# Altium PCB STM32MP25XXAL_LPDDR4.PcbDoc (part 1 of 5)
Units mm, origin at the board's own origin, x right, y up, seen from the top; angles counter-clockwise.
Board outline 125 x 95 mm, 6 copper layers (Top Layer, Signal Layer 1, Signal Layer 2, Signal Layer 3, Signal Layer 4, Bottom Layer), stack 1.403 mm thick; 182 components, 297 nets, 1131 pads, 958 vias.
Unrouted connection lines stored in the file: 5.
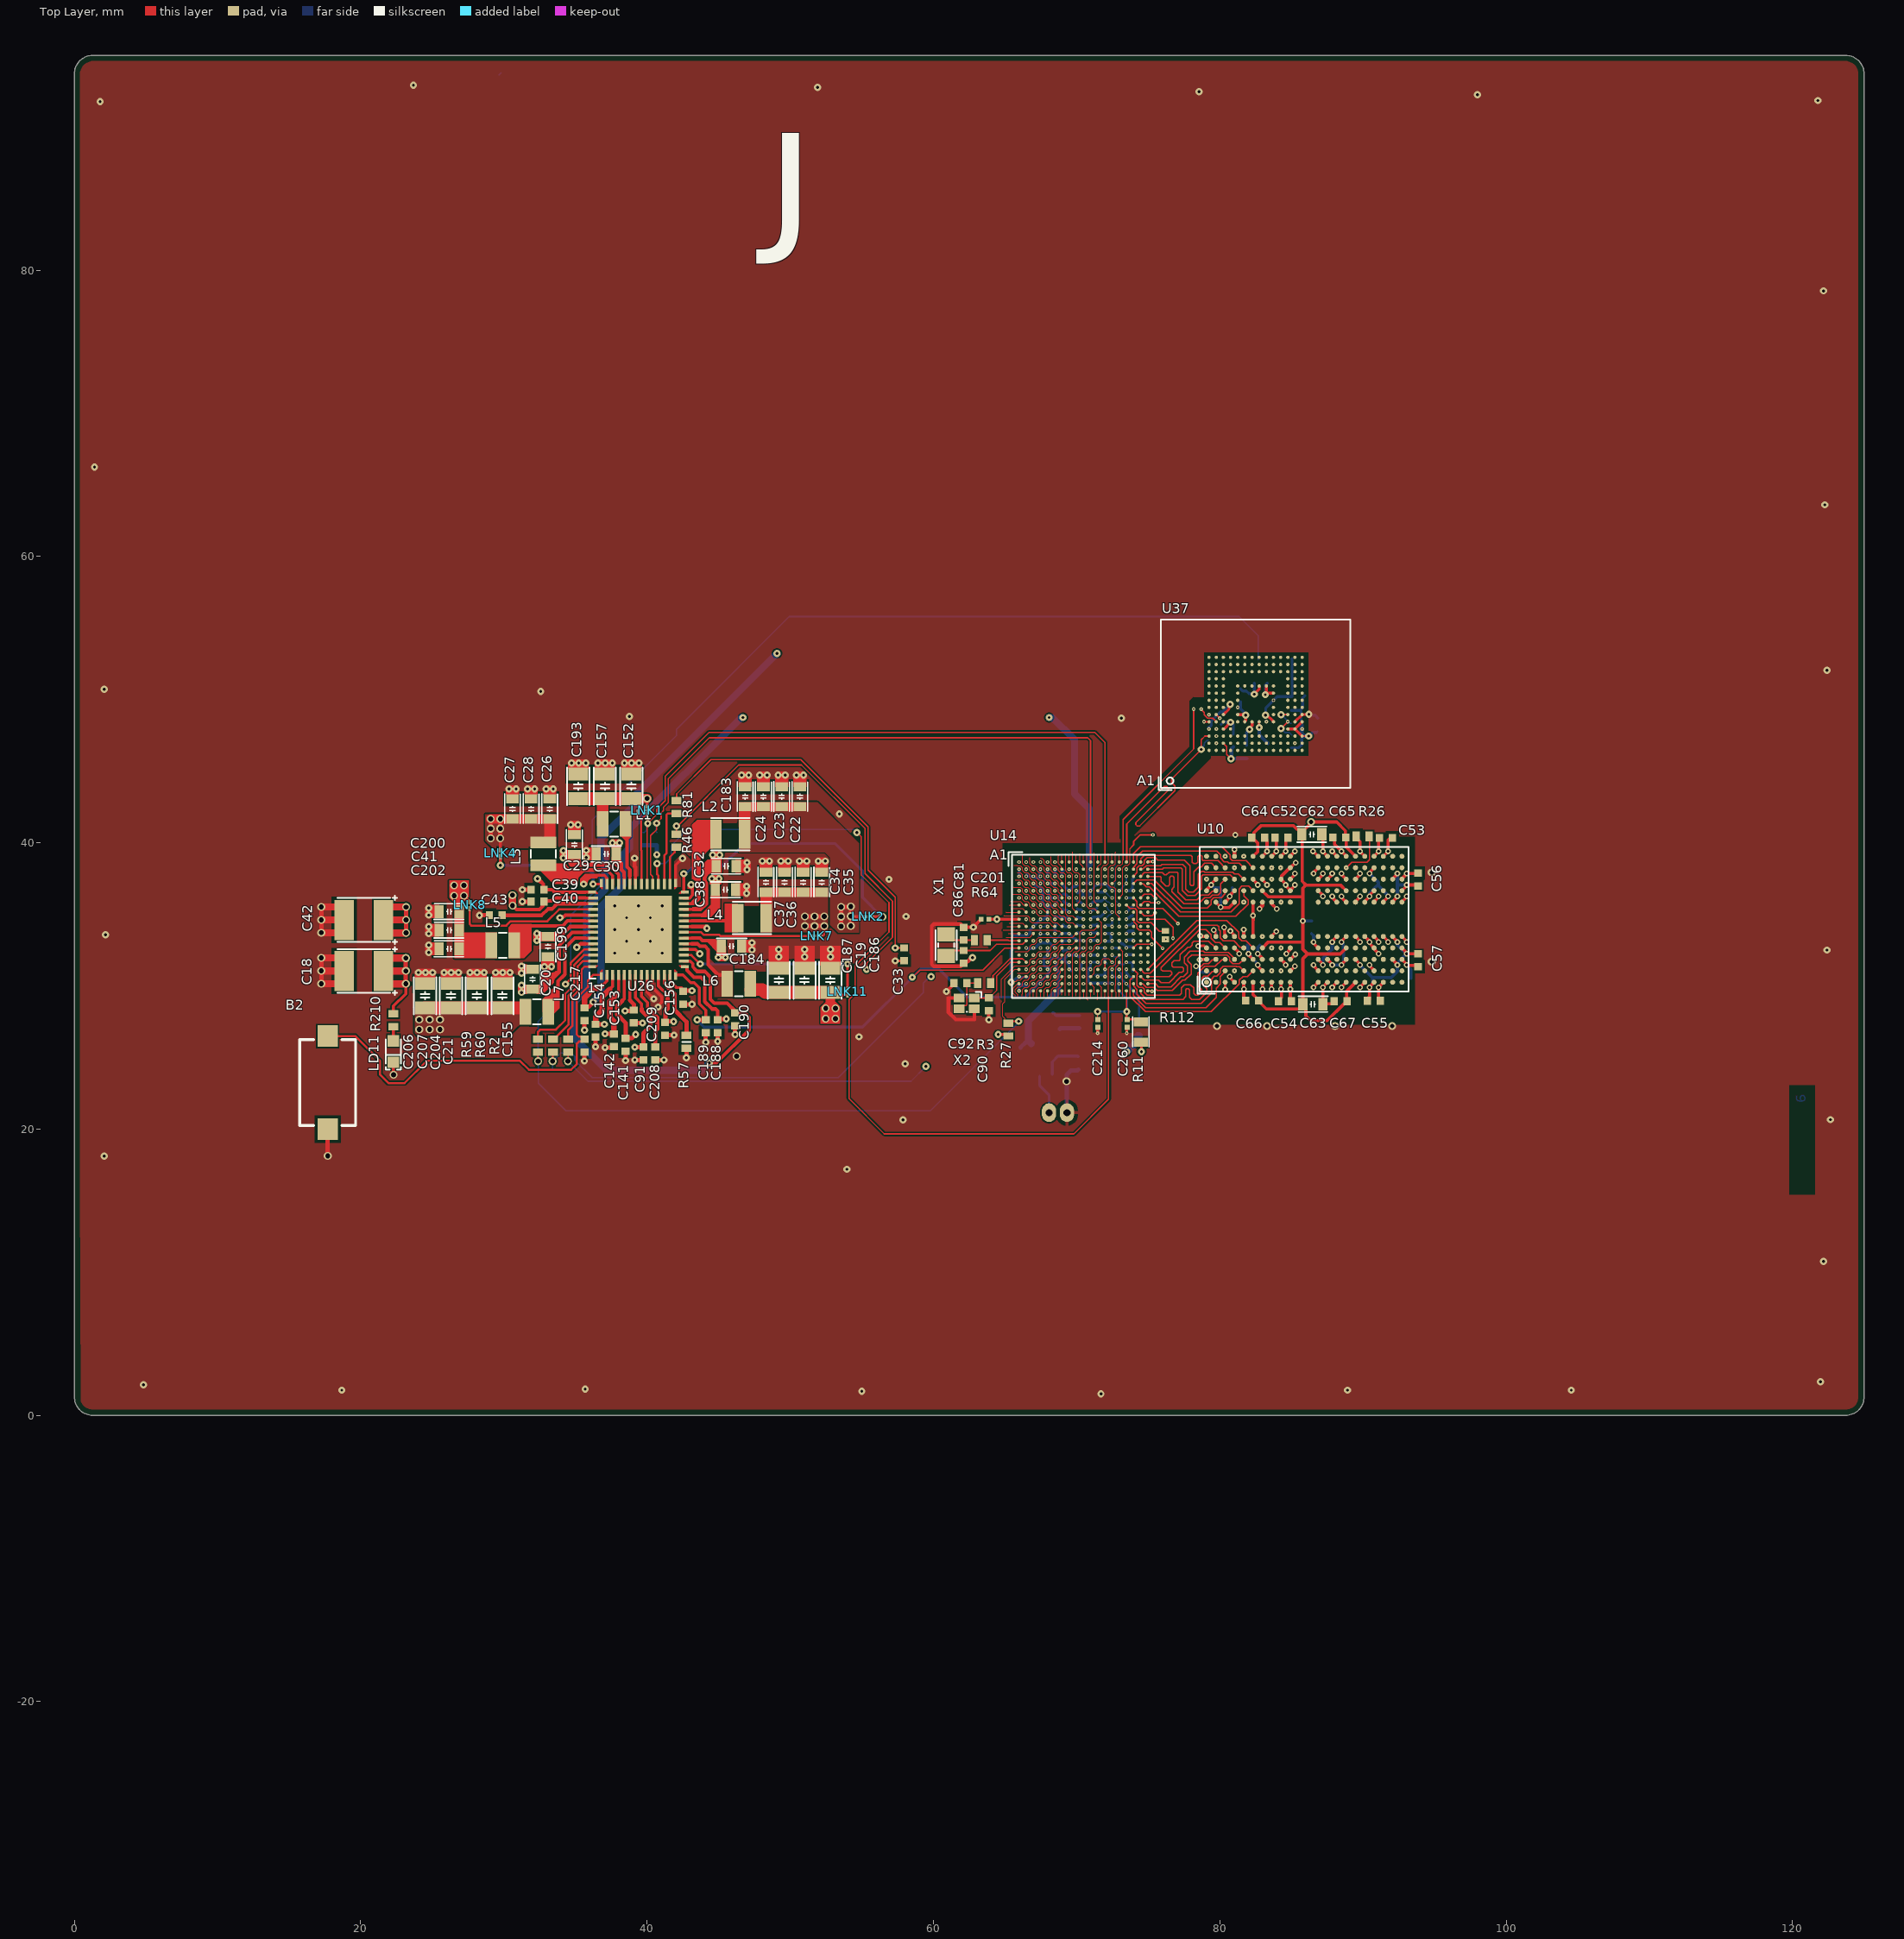
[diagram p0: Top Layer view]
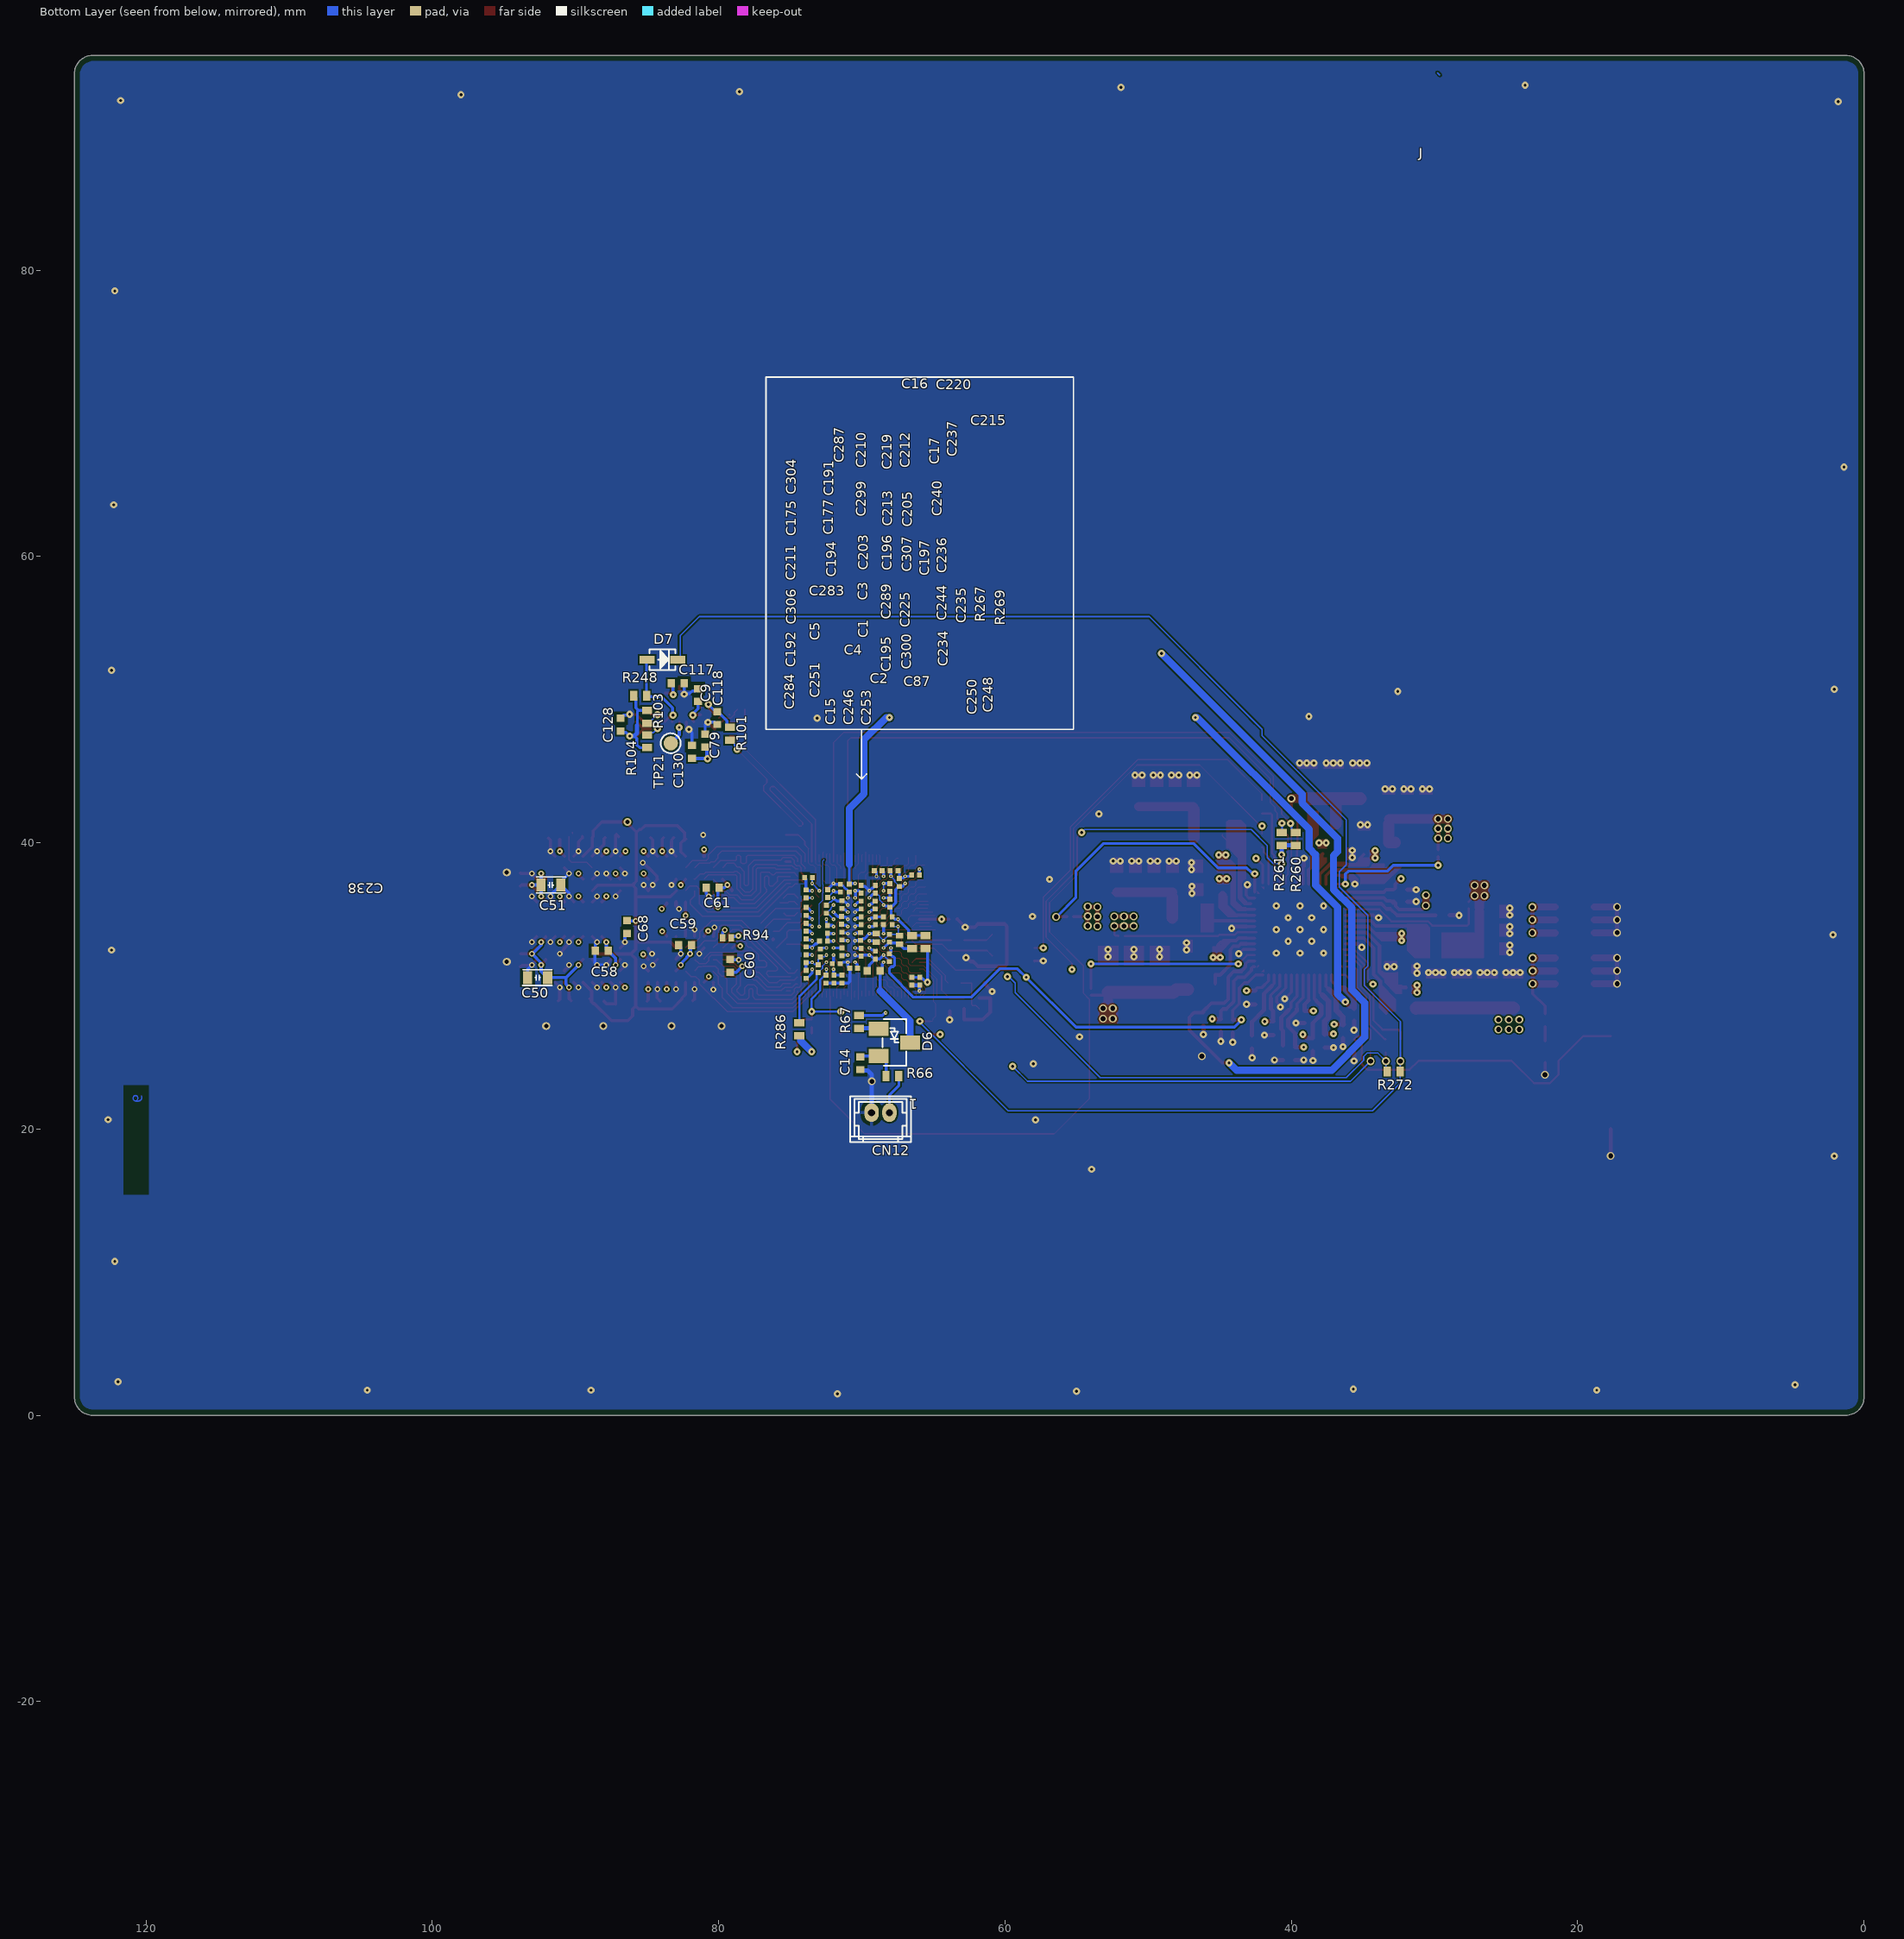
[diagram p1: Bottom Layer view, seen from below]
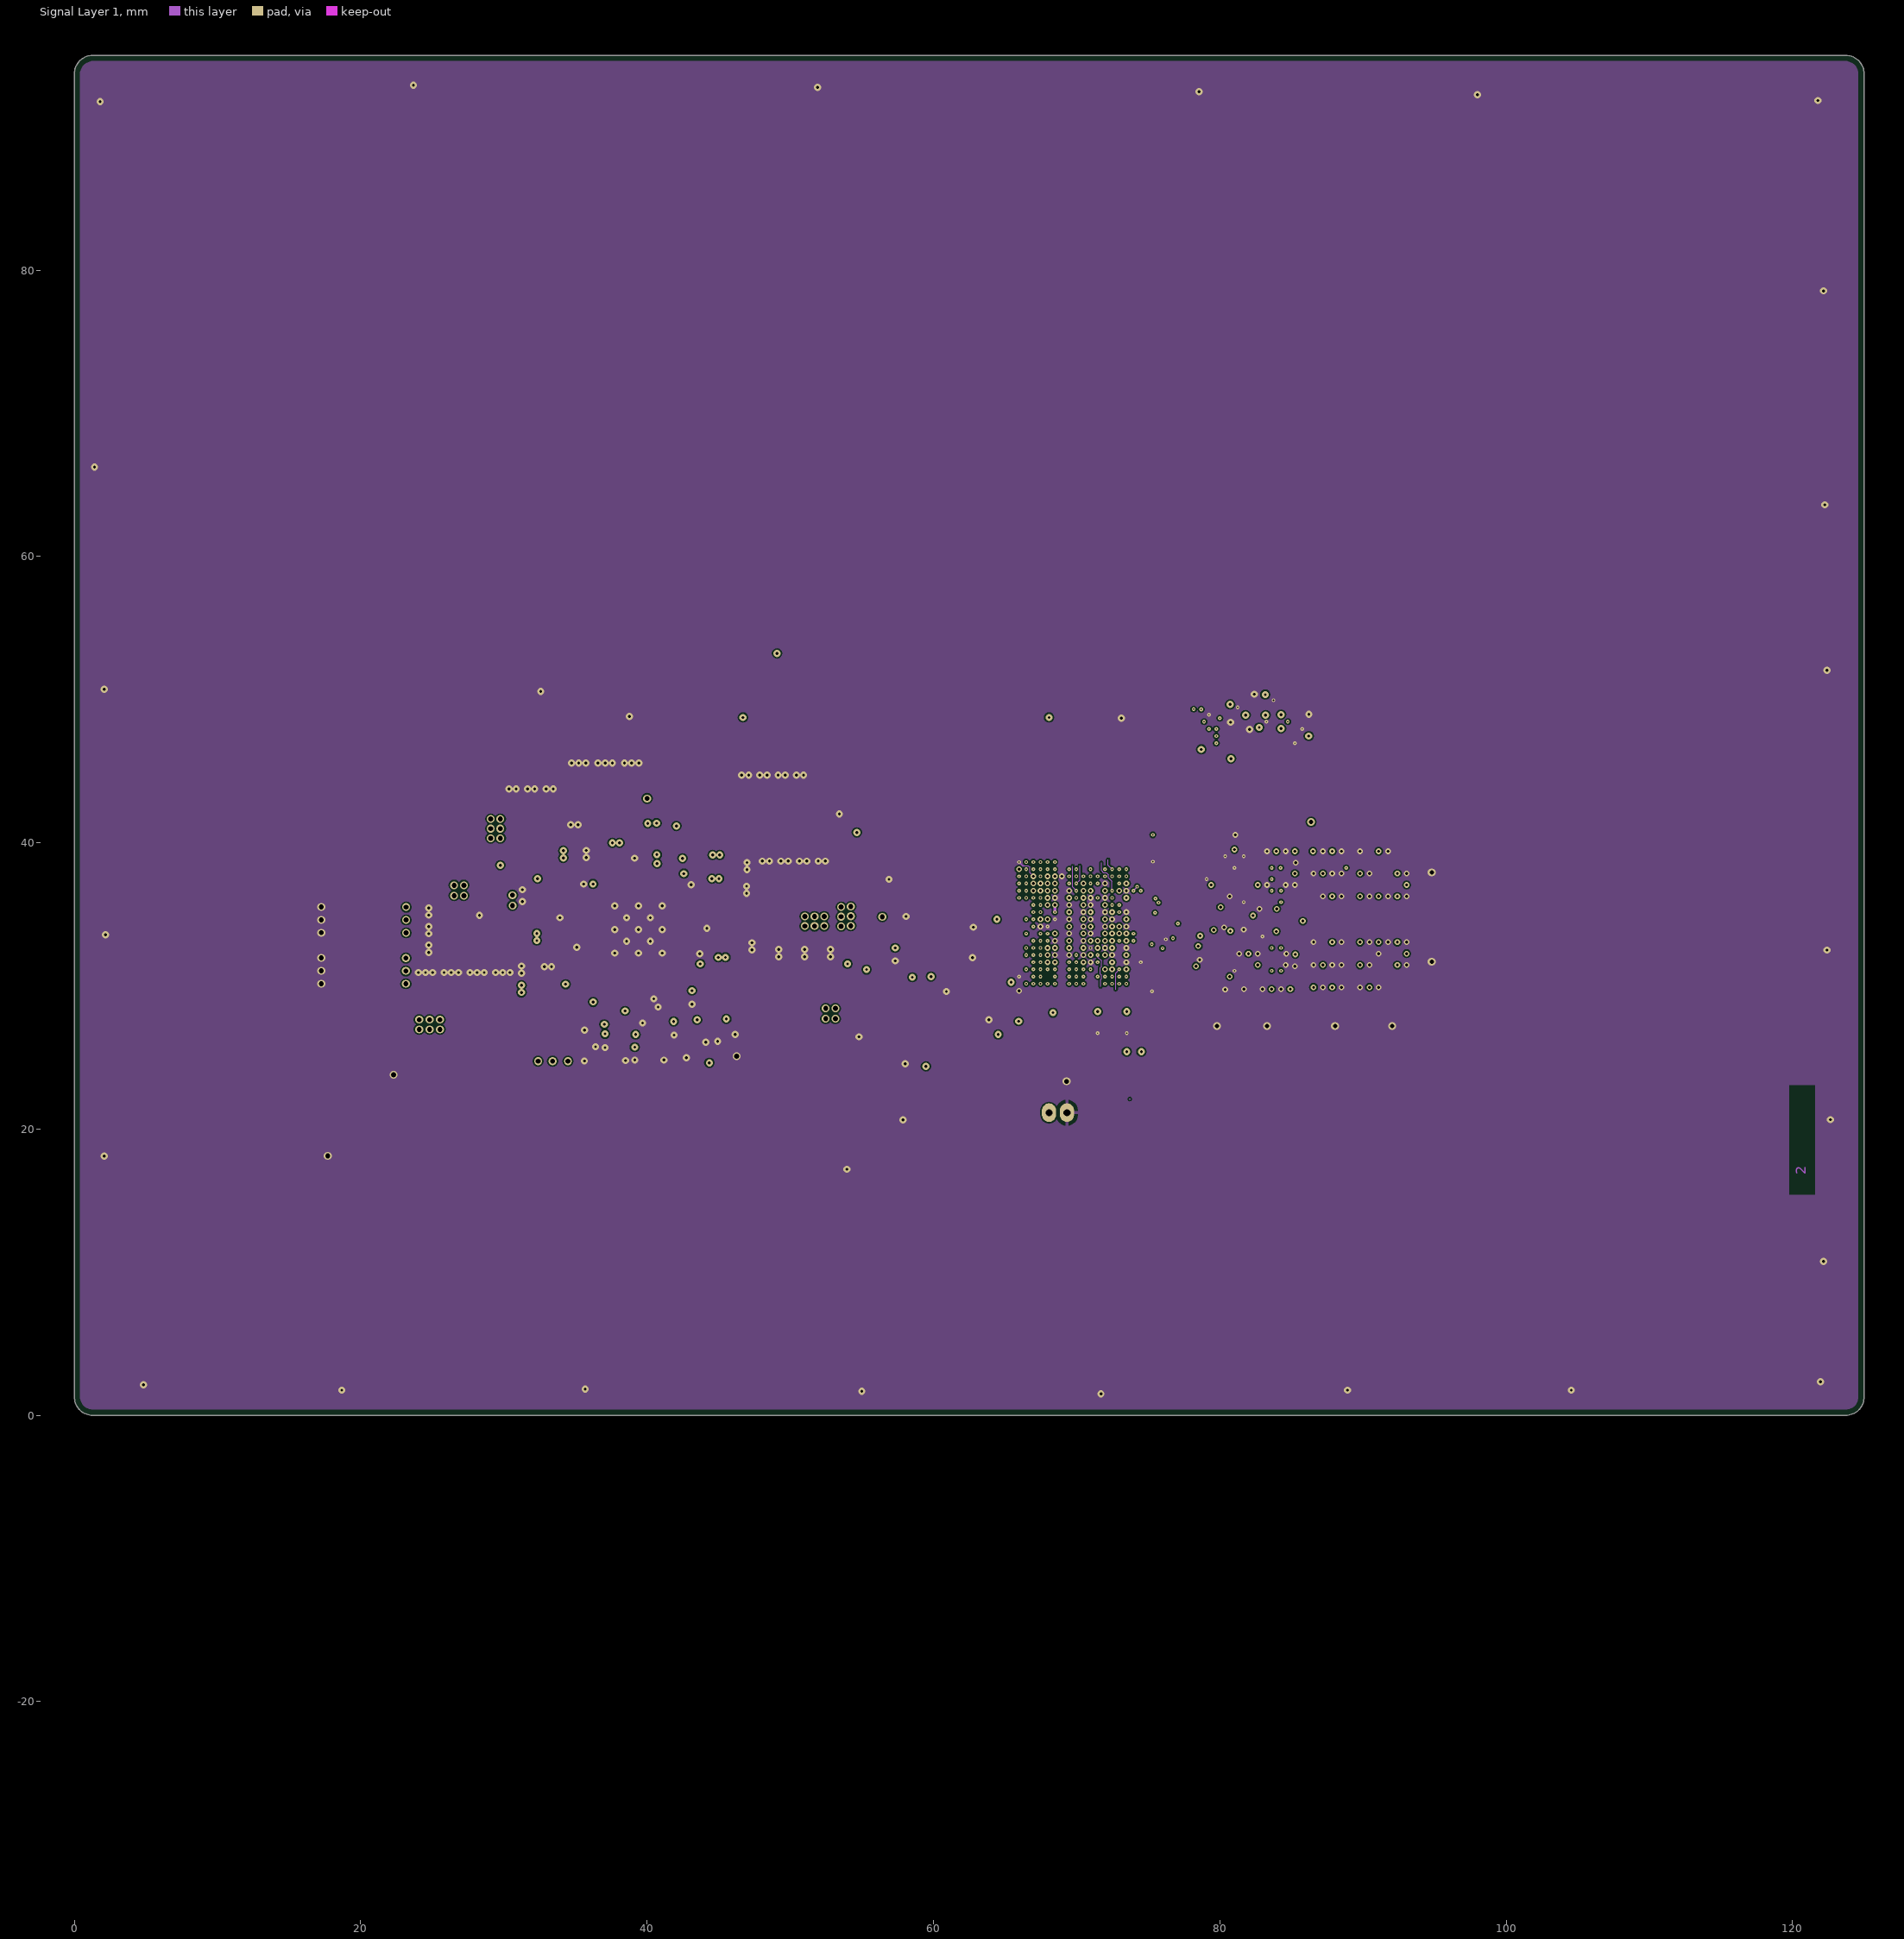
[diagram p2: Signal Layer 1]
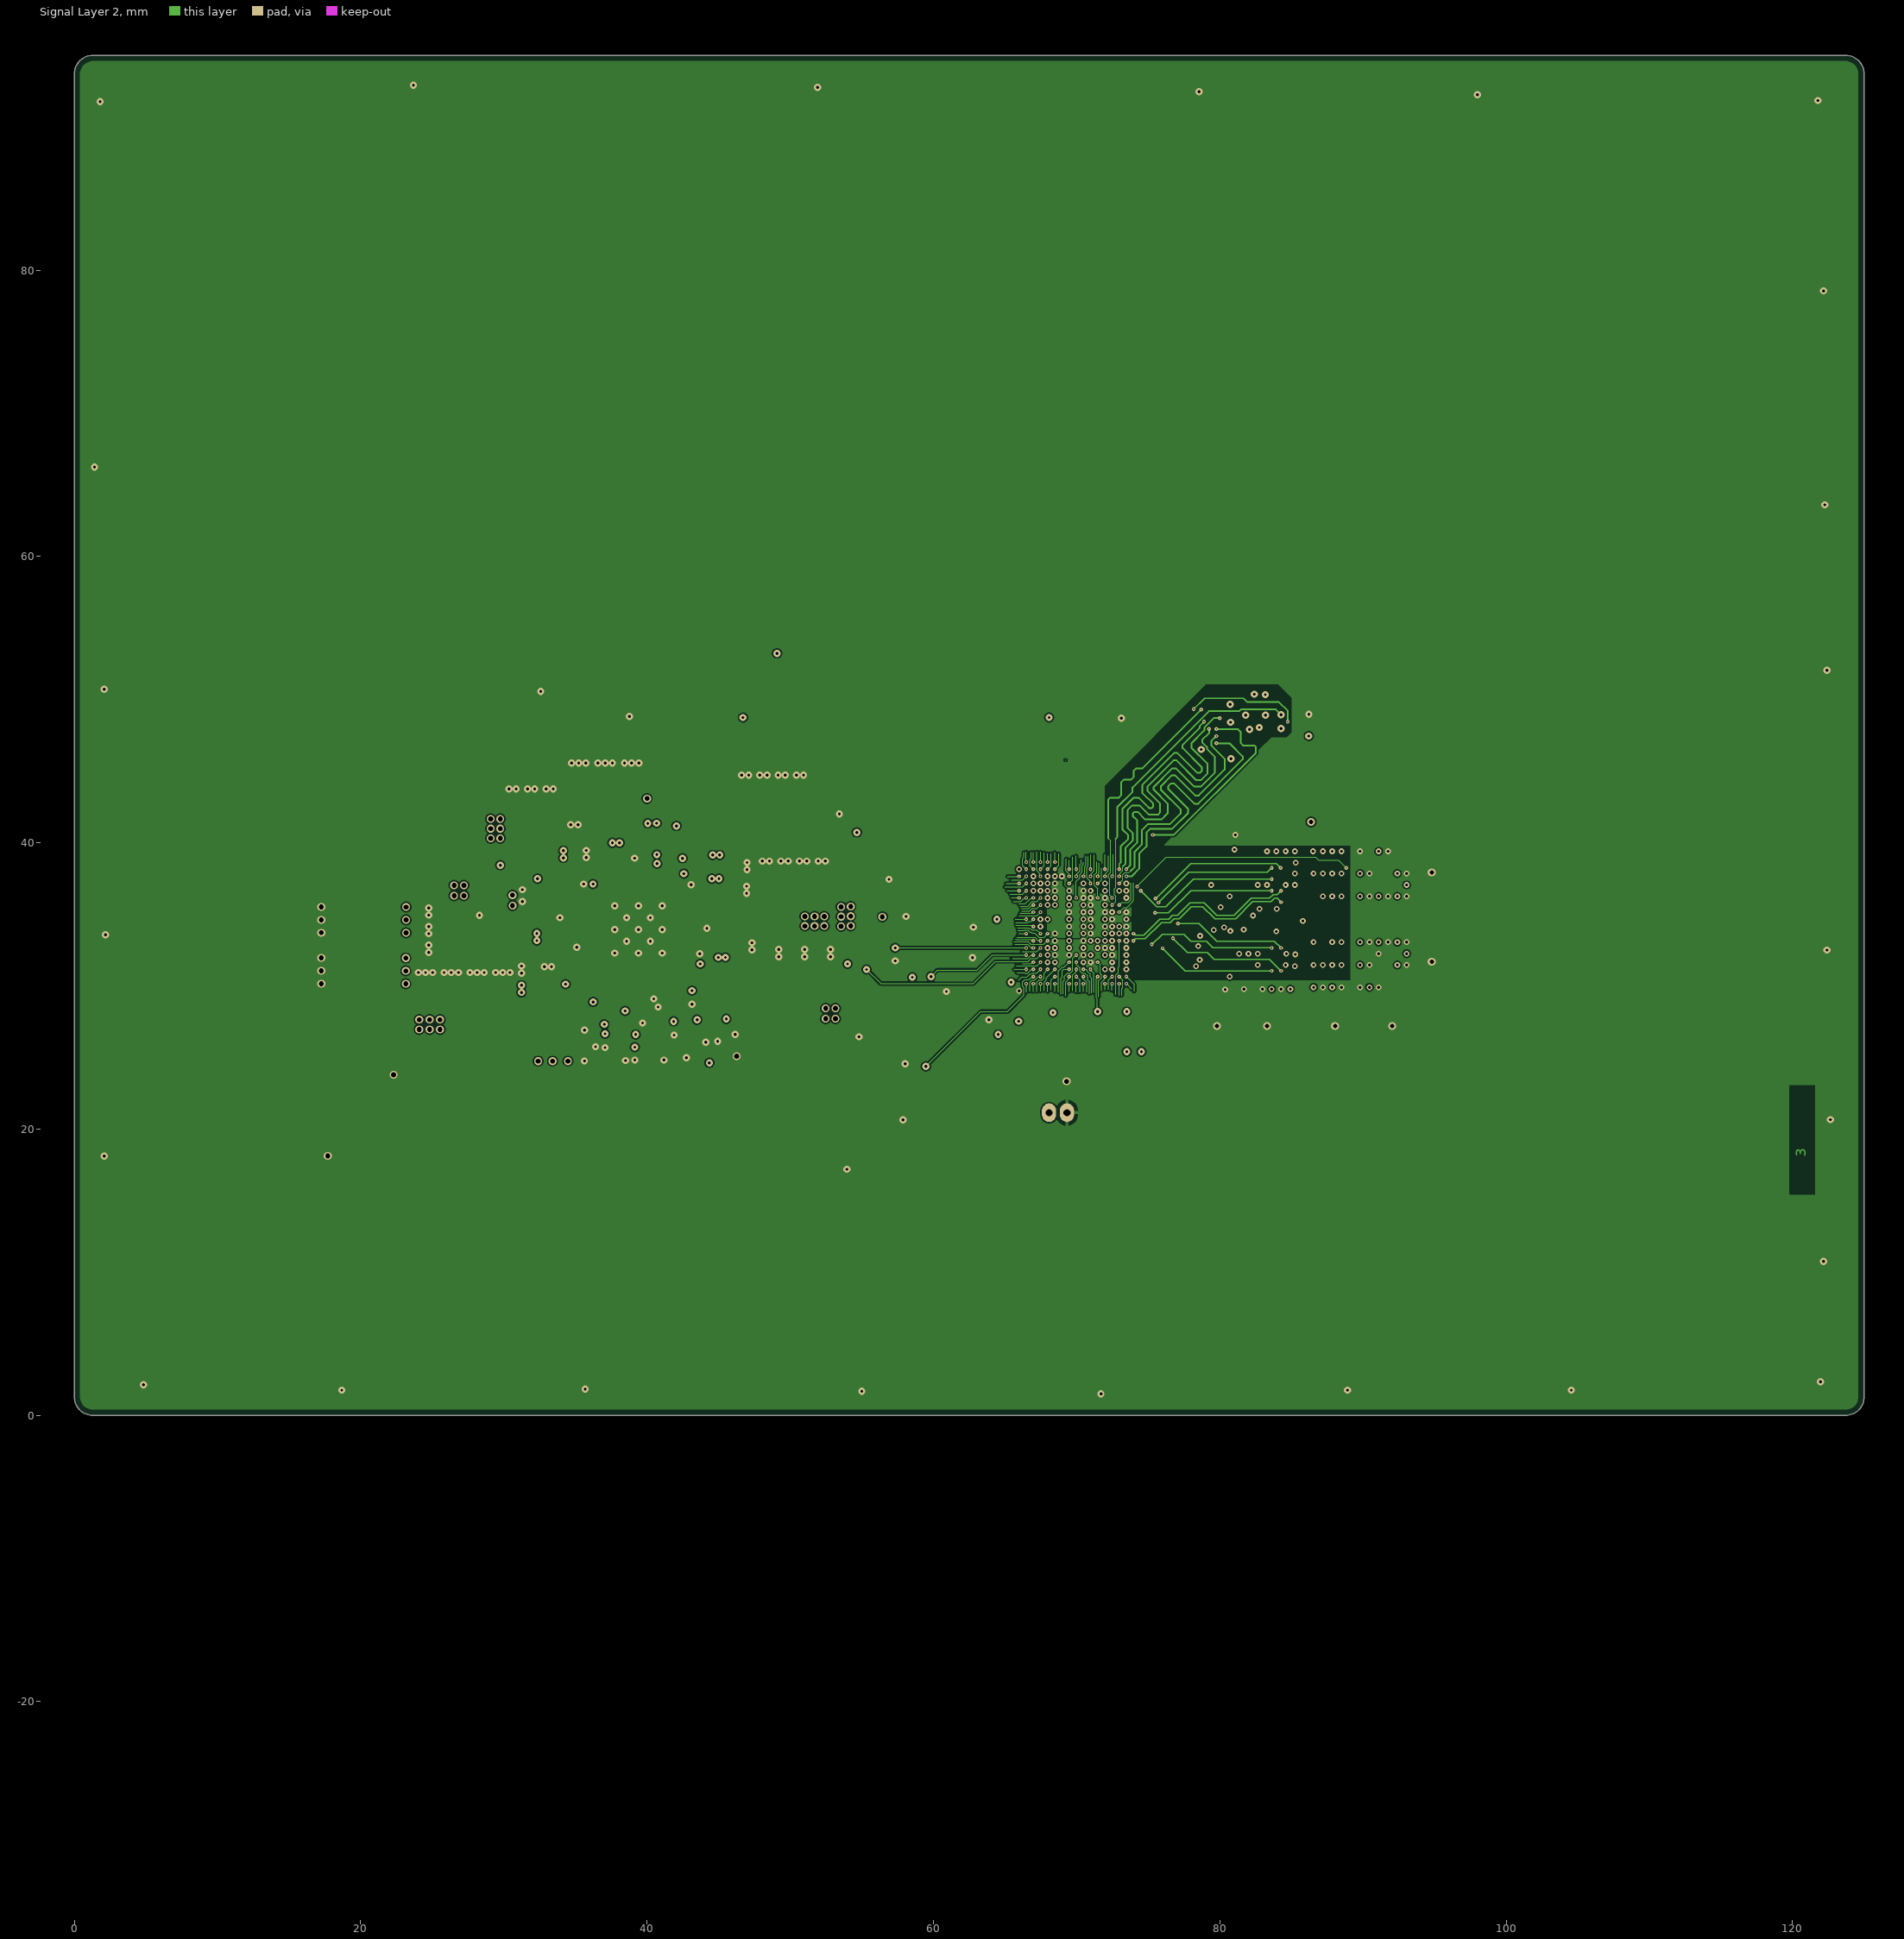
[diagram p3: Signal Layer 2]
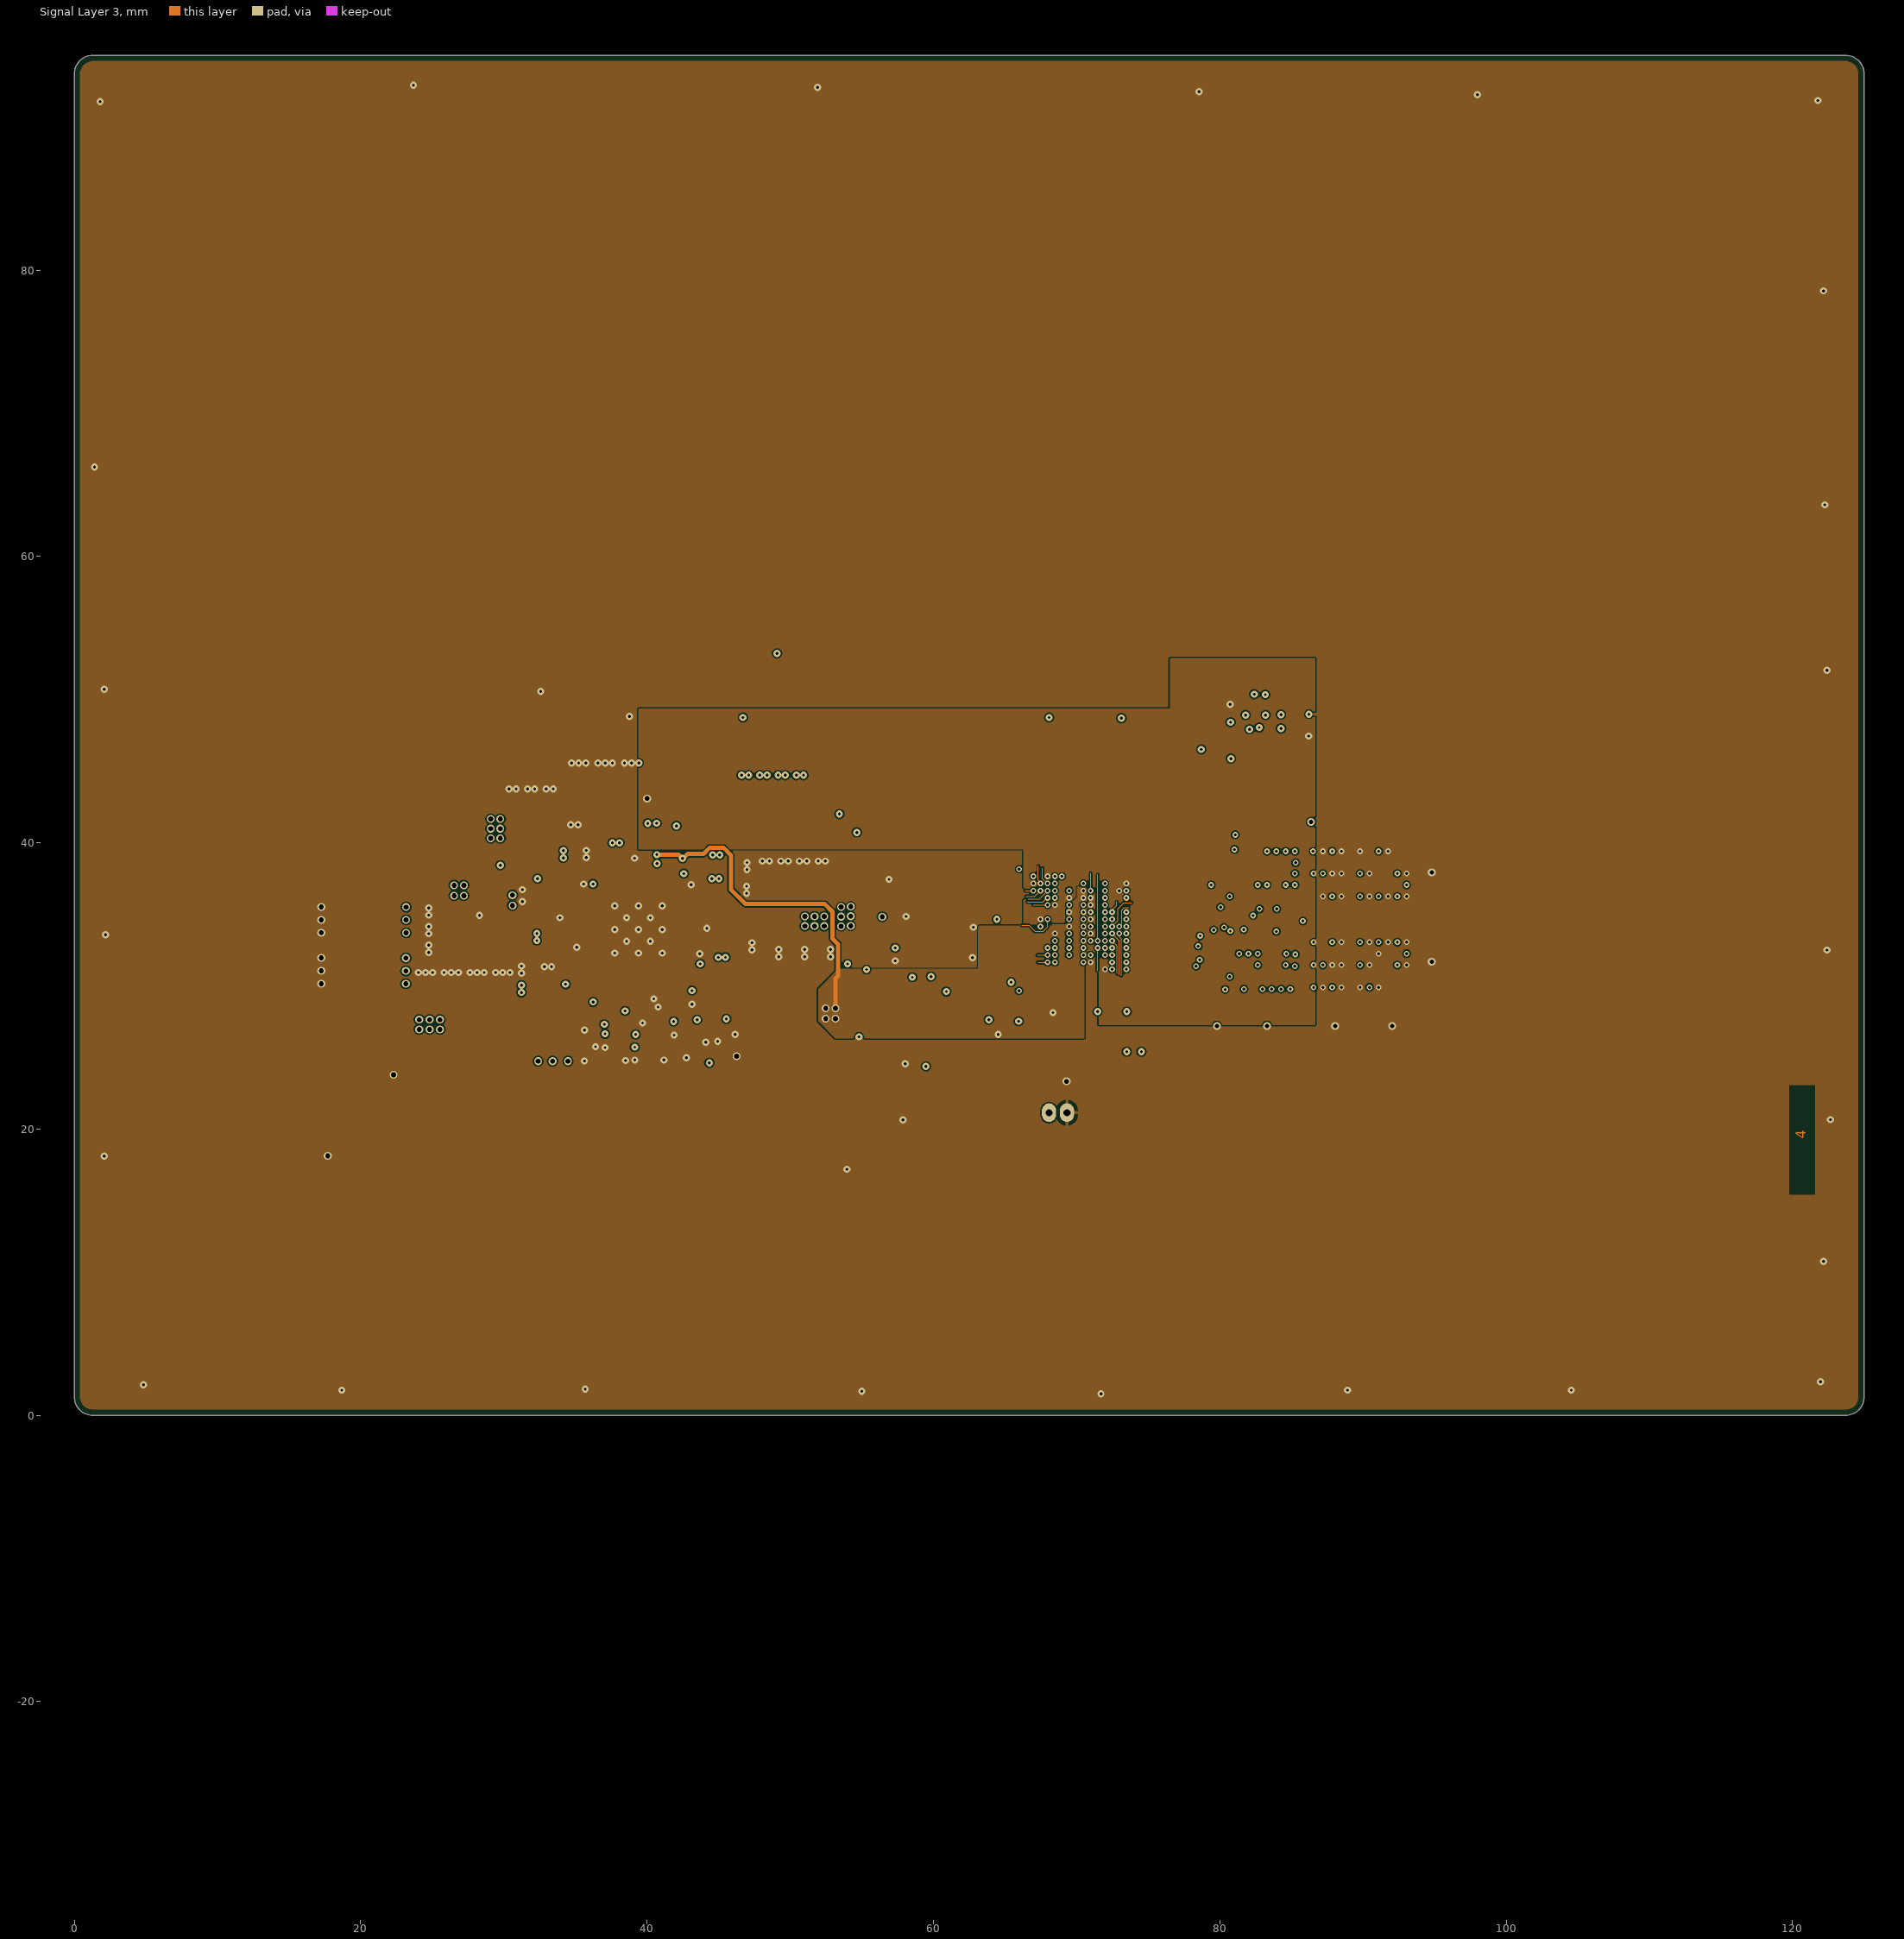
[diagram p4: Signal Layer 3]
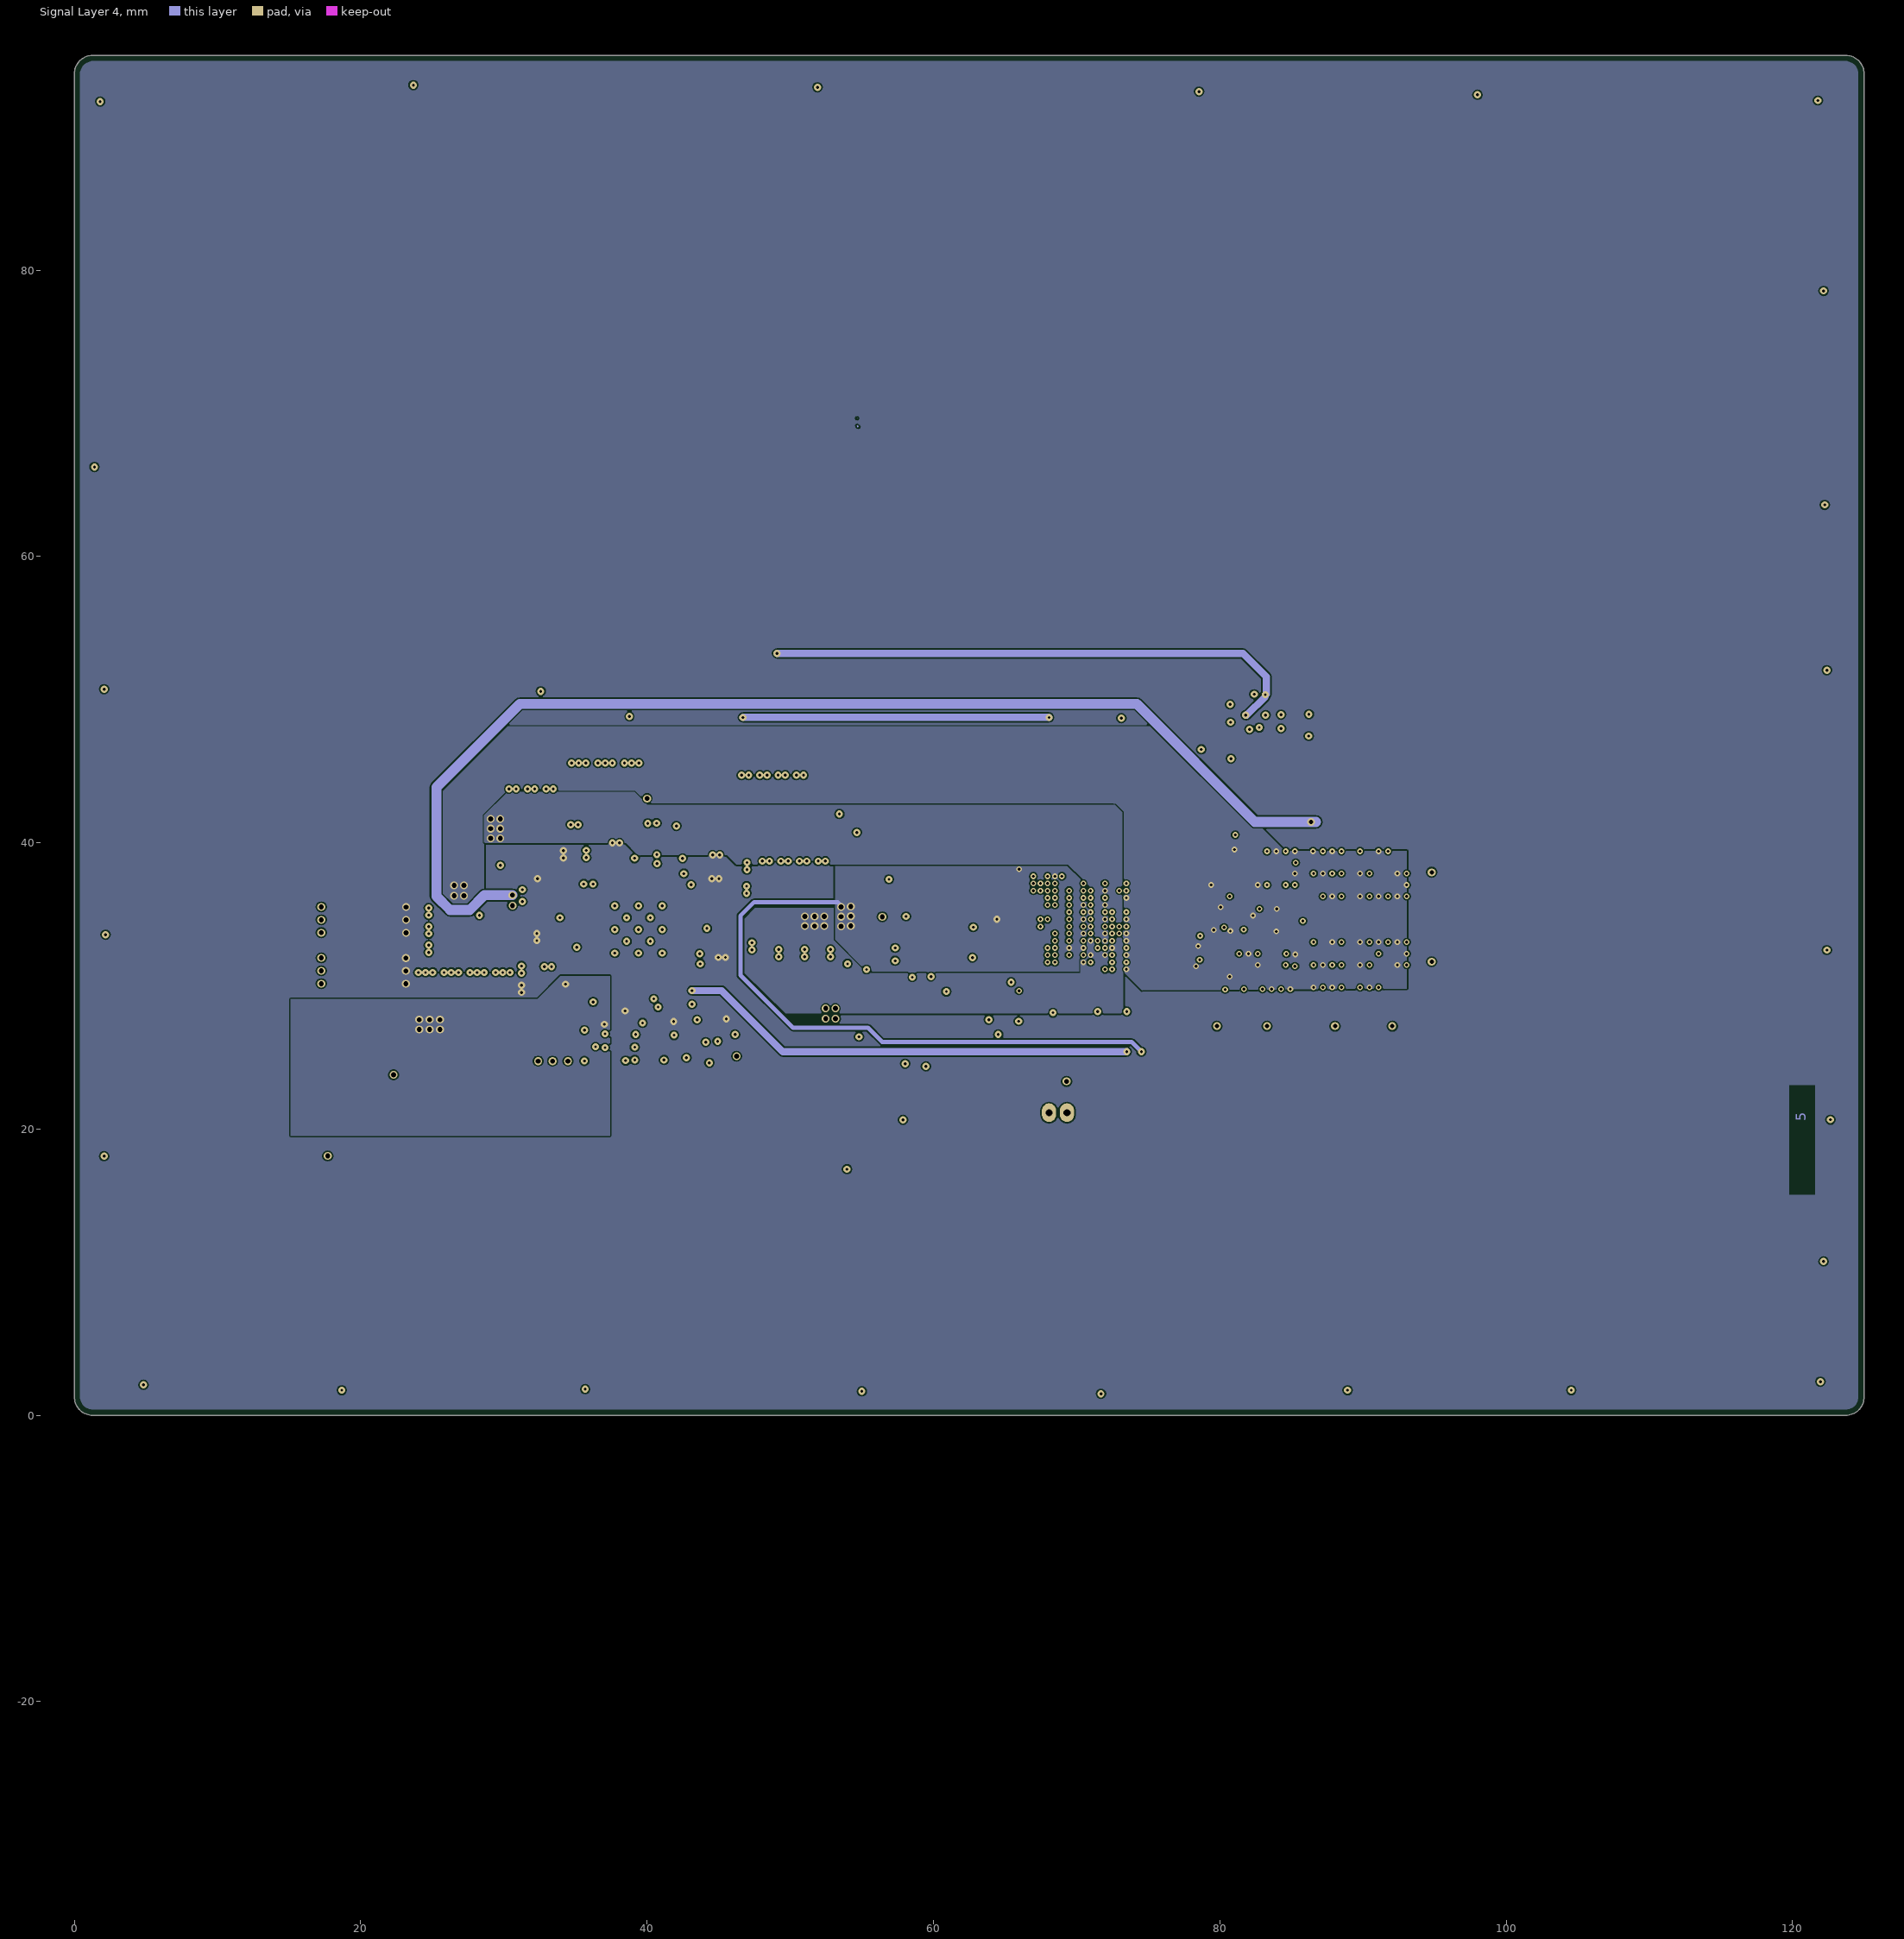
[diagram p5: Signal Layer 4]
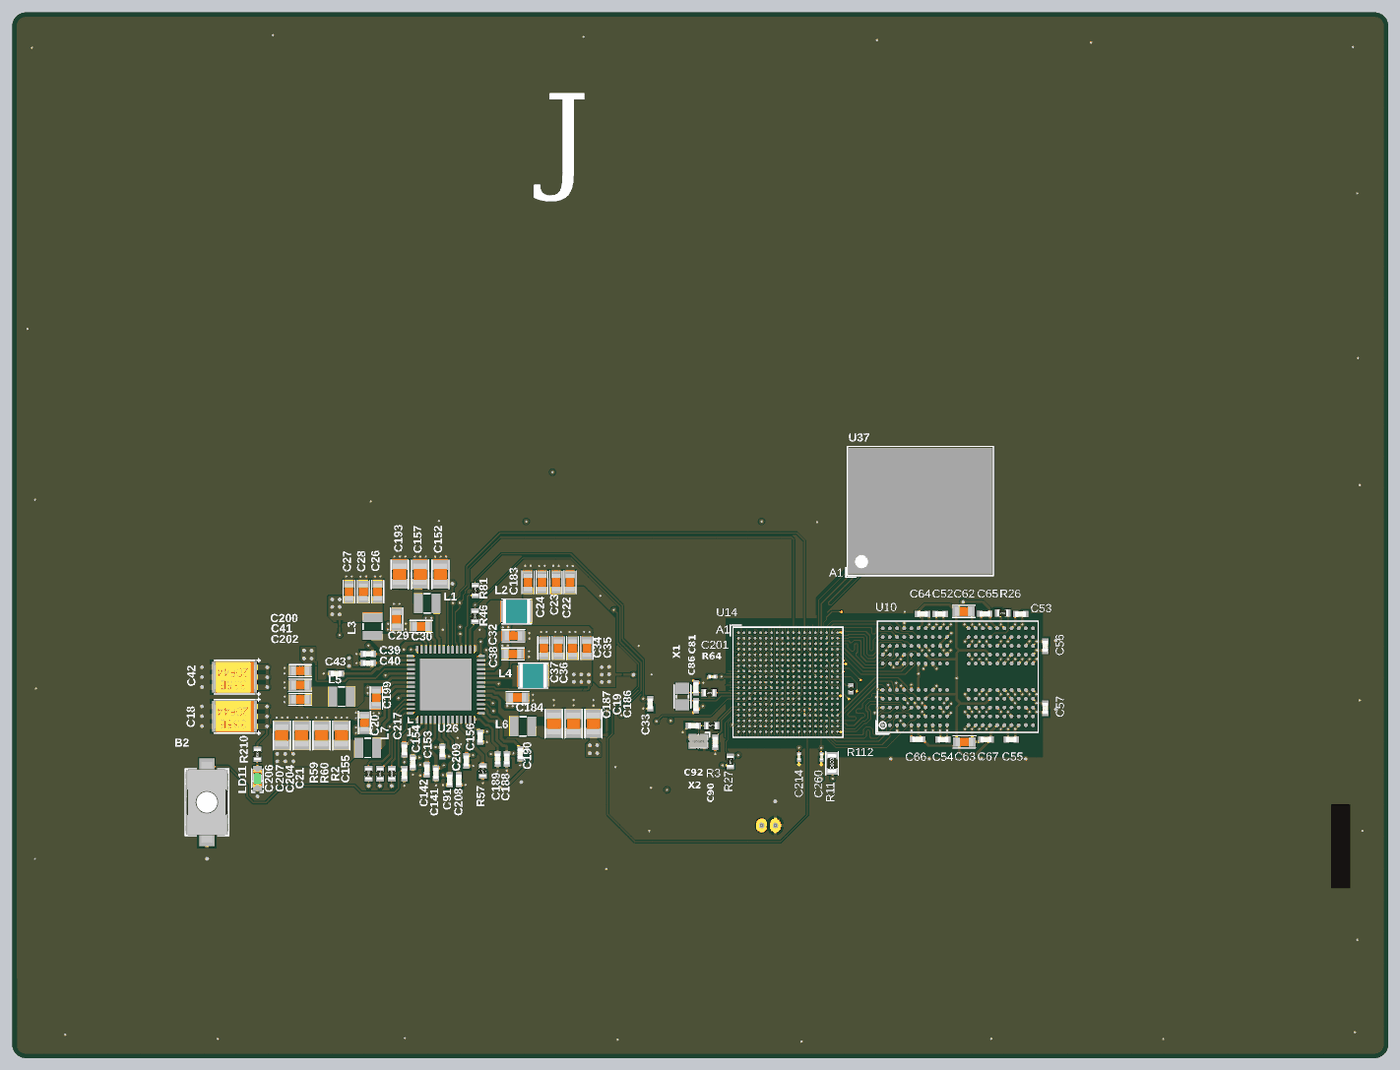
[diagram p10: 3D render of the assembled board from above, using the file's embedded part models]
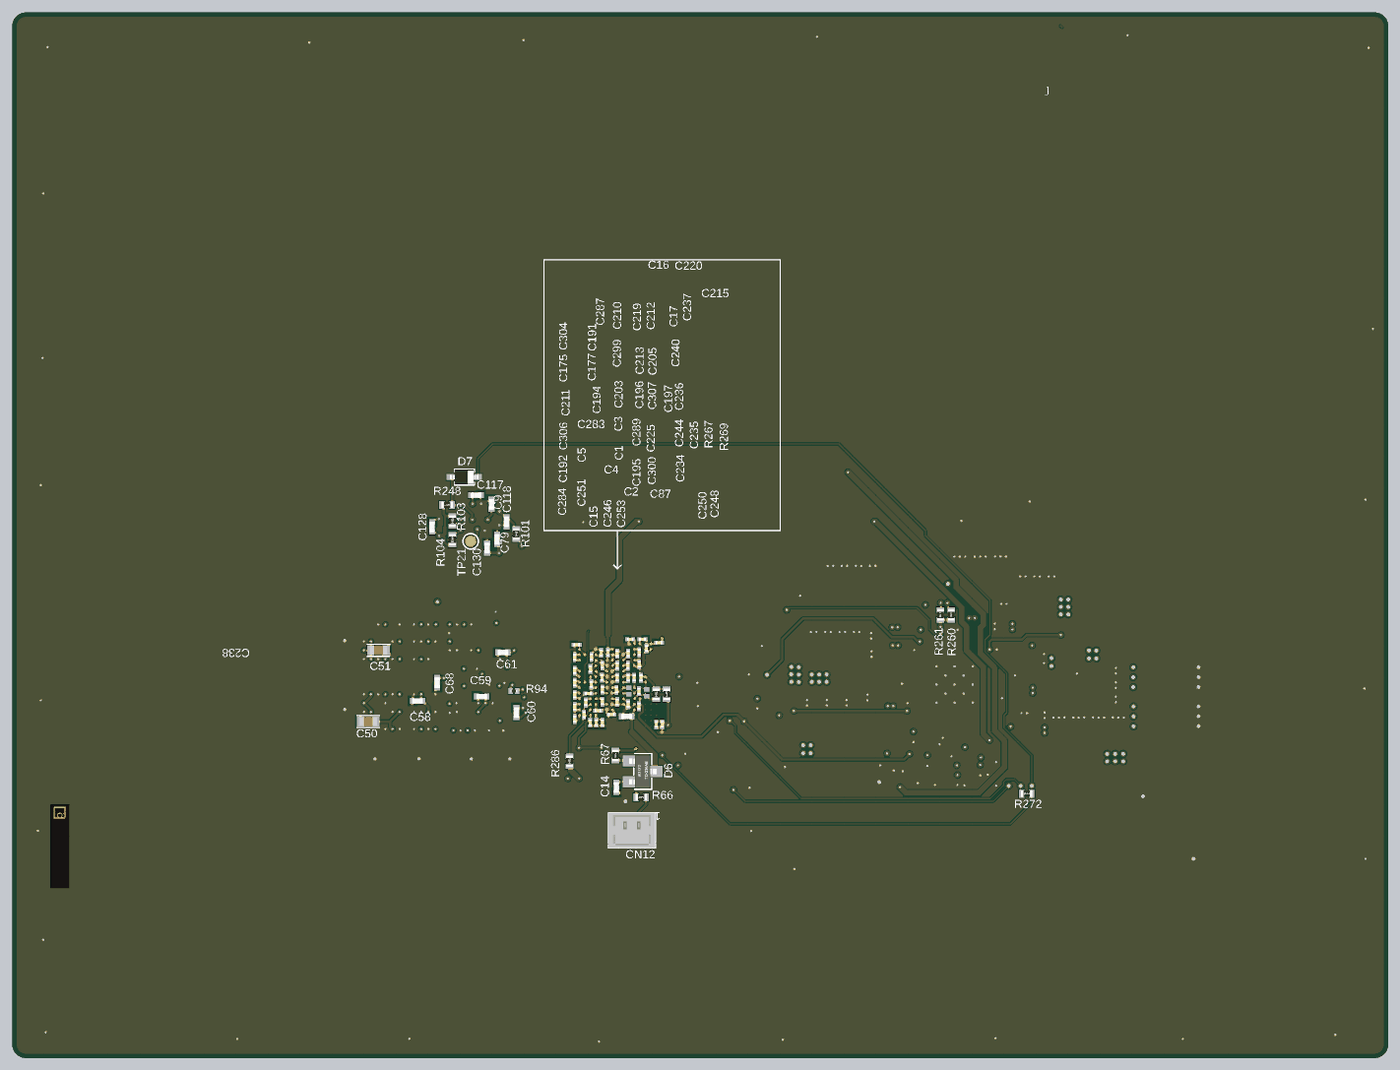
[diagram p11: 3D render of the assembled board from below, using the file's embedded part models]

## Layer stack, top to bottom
Top Solder: solder mask 0.025, Solder Resist, Dk 3.5
Top Layer: signal copper 0.046
Dielectric 1: prepreg 0.071, Dk 4.21
Signal Layer 1: signal copper 0.035
Dielectric 2: prepreg 0.094, Dk 4.09
Signal Layer 2: signal copper 0.023
Dielectric 3: core 0.865, Dk 4.68
Signal Layer 3: signal copper 0.023
Dielectric 4: prepreg 0.094, Dk 4.09
Signal Layer 4: signal copper 0.035
Dielectric5: prepreg 0.071, Dk 4.21
Bottom Layer: signal copper 0.046
Bottom Solder: solder mask 0.025, Solder Resist, Dk 3.5

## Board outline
0,1.27 ccw(c1.27,1.27) 1.27,0 123.73,0 ccw(c123.73,1.27) 125,1.27 125,93.73 ccw(c123.73,93.73) 123.73,95 1.27,95 ccw(c1.27,93.73) 0,93.73

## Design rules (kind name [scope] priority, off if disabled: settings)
BoardOutlineClearance [All] p1: gap=0.4 ignorepadtopadclearanceinfootprint=FALSE except(0: Arc-SplitContinuation Track-SplitContinuation SMDPad-SplitContinuation THPad-SplitContinuation Via-SplitContinuation Fill-SplitContinuation Poly-SplitContinuation Region-SplitContinuation Text-SplitContinuation)
Clearance [All] p1: gap=0.1 ignorepadtopadclearanceinfootprint=FALSE except(0: Arc-Hole SMDPad-Via SMDPad-Hole THPad-Hole Via-Via Via-Hole Fill-Hole Poly-Hole Region-Hole Text-Hole; 0.082: Track-Track Track-SMDPad Track-Via; 0.15: Arc-Fill Track-Fill SMDPad-Fill THPad-Fill Via-Fill Fill-Fill; 0.2: THPad-THPad)
ComponentClearance [HasFootprint('TP_SMD_1MM') vs HasFootprint('No Footprint')] p1: gap=0.2 collisioncheckmode=3 verticalgap=0.2 showdistances=FALSE
DiffPairsRouting [All] p1: maxlimit=0.16 minlimit=0.082 mostfreqgap=0.16 toplayer_mingap=0.16 toplayer_minwidth=0.075 toplayer_maxwidth=0.16 toplayer_prefwidth=0.09 midlayer1_minwidth=0.075 midlayer1_maxwidth=0.16 midlayer1_prefwidth=0.09 midlayer2_minwidth=0.075 midlayer2_maxwidth=0.16 midlayer2_prefwidth=0.09 midlayer3_minwidth=0.075 midlayer3_maxwidth=0.16 midlayer3_prefwidth=0.09 midlayer4_minwidth=0.075 midlayer4_maxwidth=0.16 midlayer4_prefwidth=0.09 bottomlayer_minwidth=0.075 bottomlayer_maxwidth=0.16 bottomlayer_prefwidth=0.09 maxuncoupledlength=12.7
FanoutControl Fanout_BGA [IsBGA] p1: bgadir=Out bgaviamode=Closest fanoutstyle=Auto fanoutdirection=Alternating viagrid=0.025 // Fanout_BGA (Default Rule)
FanoutControl Fanout_LCC [IsLCC] p2: bgadir=Out bgaviamode=Closest fanoutstyle=Auto fanoutdirection=Alternating viagrid=0.025 // Fanout_LCC (Default Rule)
FanoutControl Fanout_SOIC [IsSOIC] p3: bgadir=Out bgaviamode=Closest fanoutstyle=Auto fanoutdirection=Alternating viagrid=0.025 // Fanout_SOIC (Default Rule)
FanoutControl Fanout_Small [(CompPinCount < 5)] p4: bgadir=Out bgaviamode=Closest fanoutstyle=Auto fanoutdirection=OutThenIn viagrid=0.025 // Fanout_Small (Default Rule)
FanoutControl Fanout_Default [All] p5: bgadir=Out bgaviamode=Closest fanoutstyle=Auto fanoutdirection=Alternating viagrid=0.025 // Fanout_Default (Default Rule)
HoleSize [All] p1: absolutevalues=TRUE maxlimit=10 minlimit=0.1 maxpercent=80.000 minpercent=20.000
HoleToHoleClearance [InDrillLayerPair('Signal Layer 3 - Signal Layer 4') vs InDrillLayerPair('Signal Layer 3 - Signal Layer 4')] p1: gap=0.26 allowstackedmicrovias=TRUE
MatchedLengths MatchedLengths_ETH1 [InxSignalClass('RGMII_ETH1')] p1: tolerance=10 checknetsindiffpair=FALSE checkdiffpairvsdiffpair=TRUE checkxsignals=TRUE checkothers=TRUE
MatchedLengths MatchedLengths_ETH2 [InxSignalClass('RGMII_ETH2')] p2: tolerance=10 checknetsindiffpair=FALSE checkdiffpairvsdiffpair=TRUE checkxsignals=TRUE checkothers=TRUE
MatchedLengths MatchedLengths_SDMMC1 [InxSignalClass('SDMMC1')] p3: tolerance=5 checknetsindiffpair=FALSE checkdiffpairvsdiffpair=TRUE checkxsignals=TRUE checkothers=TRUE
MinimumSolderMaskSliver [All] p1: minsoldermaskwidth=0.1
PlaneConnect [All] p1: planeconnectstyle=Direct reliefexpansion=0.508 reliefentries=4 reliefconductorwidth=0.21 reliefairgap=0.21
PolygonConnect [All] p1: thpad.connectstyle=Relief thpad.reliefconductorwidth=0.25 thpad.reliefentries=4 thpad.polygonreliefangle="90 Angle" thpad.airgapwidth=0.25 smdpad.connectstyle=NoConnect smdpad.reliefconductorwidth=0.2 smdpad.reliefentries=4 smdpad.polygonreliefangle="90 Angle" smdpad.airgapwidth=0.2 via.connectstyle=Direct via.reliefconductorwidth=0.2 via.reliefentries=4 via.polygonreliefangle="90 Angle" via.airgapwidth=0.2
RoomDefinition "U_STM32MP25XXAL Power" [InComponentClass('U_STM32MP25XXAL Power')] p1: confinementstyle=ConfineIn formatcopy=TRUE lockcomponents=FALSE outline -865.855,-788.22 -815.055,-788.22 -815.055,-762.82 -865.855,-762.82
RoomDefinition "U_STM32MP25XXAL I_Os" [InComponentClass('U_STM32MP25XXAL I_Os')] p2: confinementstyle=ConfineIn formatcopy=TRUE lockcomponents=FALSE outline -865.855,-788.22 -815.055,-788.22 -815.055,-762.82 -865.855,-762.82
RoomDefinition U_PMIC [InComponentClass('U_PMIC')] p3: confinementstyle=ConfineIn formatcopy=TRUE lockcomponents=FALSE outline -865.855,-788.22 -815.055,-788.22 -815.055,-762.82 -865.855,-762.82
RoomDefinition U_LPDDR4_16bits [InComponentClass('U_LPDDR4_16bits')] p4: confinementstyle=ConfineIn formatcopy=TRUE lockcomponents=FALSE outline -865.855,-788.22 -815.055,-788.22 -815.055,-762.82 -865.855,-762.82
RoomDefinition U_eMMC [InComponentClass('U_eMMC')] p5: confinementstyle=ConfineIn formatcopy=TRUE lockcomponents=FALSE outline -865.855,-788.22 -815.055,-788.22 -815.055,-762.82 -865.855,-762.82
RoutingVias [All] p1: holewidth=0.2 width=0.4 viastyle="Through Hole" minholewidth=0.1 minwidth=0.26 maxholewidth=0.35 maxwidth=0.6
SilkToSilkClearance [All] p1: silktosilkclearance=0.2
SilkToSolderMaskClearance [IsPad] p1: minsilkscreentomaskgap=0.2 clearancetoexposedcopper=TRUE
SolderMaskExpansion [All] p1: expansion=0.05 istentingtop=FALSE
Width [All] p1: maxlimit=10 minlimit=0.075 preferedwidth=0.1 toplayer_prefwidth=0.09 midlayer2_prefwidth=0.09 minimp=50.000000 maximp=50.000000 favimp=50.000000
17 further rules are at their usual default settings.

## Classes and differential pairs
net class eMMC.SDMMC2_D[0..7]: eMMC.SDMMC2_D0 eMMC.SDMMC2_D1 eMMC.SDMMC2_D2 eMMC.SDMMC2_D3 eMMC.SDMMC2_D4 eMMC.SDMMC2_D5 eMMC.SDMMC2_D6 eMMC.SDMMC2_D7
component class "U_STM32MP25XXAL Power": C1 C2 C3 C4 C5 C14 C15 C16 C17 C87 C175 C177 C191 C192 C194 C195 C196 C197 C201 C203 C205 C210 C211 C212 C213 C214 C215 C219 C220 C225 C234 C235 C236 C237 C238 C240 C244 C246 C248 C250 C251 C253 C260 C283 C284 C287 C289 C299 C300 C304 C306 C307 CN12 D6 R11 R66 R67 R267 R269 R286
component class "U_STM32MP25XXAL I_Os": C33 C81 C86 C90 C92 R3 R27 R64 R260 R261 R272 U14 X1 X2
component class U_PMIC: B2 C18 C19 C20 C21 C22 C23 C24 C26 C27 C28 C29 C30 C32 C34 C35 C36 C37 C38 C39 C40 C41 C42 C43 C91 C141 C142 C152 C153 C154 C155 C156 C157 C183 C184 C186 C187 C188 C189 C190 C193 C199 C200 C202 C204 C206 C207 C208 C209 C217 L1 L2 L3 L4 L5 L6 L7 LD11 LNK1 LNK2 LNK4 LNK7 LNK8 LNK11 R2 R46 R57 R59 R60 R81 R210 U26
component class U_LPDDR4_16bits: C50 C51 C52 C53 C54 C55 C56 C57 C58 C59 C60 C61 C62 C63 C64 C65 C66 C67 C68 R26 R94 R112 U10
component class U_eMMC: C9 C79 C117 C118 C128 C130 D7 R101 R103 R104 R248 TP21 U37
differential pair DDR_DQS1: +DDR_DQS1_P -DDR_DQS1_N
differential pair DDR_DQS0: +DDR_DQS0_P -DDR_DQS0_N
differential pair DDR_CLK: +DDR_CLK_P -DDR_CLK_N

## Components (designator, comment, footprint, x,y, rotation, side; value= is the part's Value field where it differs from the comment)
B2 "SW_PUSH_SMD_2P" SWI_WE_434121025816 17.693,23.243 r90 top value=434121025816
C1 "1uF" C0201_MURATA_GRM033_H0P3 71.4,32.38 r270 bottom
C2 "1uF" C0201_MURATA_GRM033_H0P3 70.575,31.225 r180 bottom
C3 "1uF" C0201_MURATA_GRM033_H0P3 71.4,33.48 r270 bottom
C4 "1uF" C0201_MURATA_GRM033_H0P3 71.795,31.555 r0 bottom
C5 "1uF" C0201_MURATA_GRM033_H0P3 72.9,32.3 r90 bottom
C9 "Capacitor" C0402 81.451,50.313 r270 bottom value=100nF
C14 "Capacitor" C0402 70.117,24.601 r90 bottom value=2.2uF
C15 "Capacitor" C0201_MURATA_GRM033_H0P3 72.5,30.47 r90 bottom value=1uF
C16 "Capacitor" C0201_MURATA_GRM033_H0P3 68.855,38.05 r180 bottom value=100nF
C17 "Capacitor" C0201_MURATA_GRM033_H0P3 68.045,36.875 r90 bottom value=100nF
C18 "Cap_POL_TANA" CPOL_TCJ-B_1210_H210 20.209,31.045 r180 top value=100uF
C19 "Capacitor" C0805 50.998,30.389 r270 top value=22uF
C20 "Capacitor" C0603 31.998,30.464 r270 top value=10uF
C21 "Capacitor" C0805 29.898,29.312 r270 top value=22uF
C22 "Capacitor" C0603 50.673,43.214 r270 top value=22uF
C23 "Capacitor" C0603 49.398,43.214 r270 top value=22uF
C24 "Capacitor" C0603 48.123,43.214 r270 top value=22uF
C26 "Capacitor" C0603 33.198,42.364 r270 top value=22uF
C27 "Capacitor" C0603 30.598,42.364 r270 top value=22uF
C28 "Capacitor" C0603 31.898,42.364 r270 top value=22uF
C29 "Capacitor" C0603 34.923,39.864 r270 top value=10uF
C30 "Capacitor" C0603 37.148,39.214 r0 top value=10uF
C32 "Capacitor" C0603 45.523,38.364 r180 top value=10uF
C33 "Capacitor" C0402 57.955,32.2 r90 top value=10nF
C34 "Capacitor" C0603 50.898,37.239 r270 top value=22uF
C35 "Capacitor" C0603 52.198,37.239 r270 top value=22uF
C36 "Capacitor" C0603 49.598,37.239 r270 top value=22uF
C37 "Capacitor" C0603 48.298,37.239 r270 top value=22uF
C38 "Capacitor" C0603 45.473,36.714 r180 top value=10uF
C39 "Capacitor" C0402 32.343,36.714 r0 top value=1uF
C40 "Capacitor" C0402 32.343,35.889 r0 top value=10uF
C41 "Capacitor" C0603 26.173,33.889 r0 top value=22uF
C42 "Cap_POL_TANA" CPOL_TCJ-B_1210_H210 20.209,34.607 r180 top value=100uF
C43 "Capacitor" C0402 29.433,34.939 r0 top value=1uF
C50 "Capacitor" C0603 92.65,30.575 r180 bottom value=10uF
C51 "Capacitor" C0603 91.725,37.05 r0 bottom value=10uF
C52 "Capacitor" C0402 84.3,40.35 r180 top value=100nF
C53 "Capacitor" C0402 91.6,40.335 r0 top value=100nF
C54 "Capacitor" C0402 84.55,28.935 r180 top value=100nF
C55 "Capacitor" C0402 90.75,28.95 r0 top value=100nF
C56 "Capacitor" C0402 93.85,37.42 r90 top value=100nF
C57 "Capacitor" C0402 93.85,31.784 r270 top value=100nF
C58 "Capacitor" C0402 88.175,32.45 r0 bottom value=100nF
C59 "Capacitor" C0402 82.35,32.85 r0 bottom value=100nF
C60 "Capacitor" C0402 79.2,31.4 r90 bottom value=100nF
C61 "Capacitor" C0402 80.425,36.85 r0 bottom value=100nF
C62 "Capacitor" C0603 86.425,40.585 r180 top value=10uF
C63 "Capacitor" C0603 86.5,28.72 r180 top value=10uF
C64 "Capacitor" C0402 82.69,40.35 r180 top value=100nF
C65 "Capacitor" C0402 88.35,40.36 r0 top value=100nF
C66 "Capacitor" C0402 82.25,28.97 r0 top value=100nF
C67 "Capacitor" C0402 88.45,28.935 r0 top value=100nF
C68 "Capacitor" C0402 86.4,34.1 r90 bottom value=100nF
C79 "Capacitor" C0402 80.946,47.138 r270 bottom value=2.2uF
C81 "Capacitor" C0402 62.112,33.645 r90 top value=6.8pF
C86 "Capacitor" C0402 62.112,32.02 r270 top value=6.8pF
C87 "Capacitor" C0402 69.175,31.05 r180 bottom value=100nF
C90 "Capacitor" C0402 63.865,28.706 r90 top value=6.8pF
C91 "Capacitor" C0402 39.748,25.269 r270 top value=4.7uF
C92 "Capacitor" C0402 61.881,30.192 r180 top value=6.8pF
C117 "Capacitor" C0402 82.861,51.148 r0 bottom value=2.2uF
C118 "Capacitor" C0402 80.096,48.713 r90 bottom value=100nF
C128 "Capacitor" C0402 86.85,48.25 r270 bottom value=2.2uF
C130 "Capacitor" C0402 81.864,46.338 r270 bottom value=100nF
C141 "Capacitor" C0402 38.498,25.889 r270 top value=4.7uF
C142 "Capacitor" C0402 37.673,26.199 r270 top value=4.7uF
C152 "Capacitor" C0805 38.898,43.939 r270 top value=22uF
C153 "Capacitor" C0402 39.073,27.859 r90 top value=1uF
C154 "Capacitor" C0402 36.398,26.864 r90 top value=1uF
C155 "Capacitor" C0402 35.625,25.834 r90 top value=10nF
C156 "Capacitor" C0402 42.523,29.159 r90 top value=4.7uF
C157 "Capacitor" C0805 37.048,43.939 r270 top value=22uF
C175 "Capacitor" C0201_MURATA_GRM033_H0P3 73.9,35.2 r90 bottom value=1uF
C177 "Capacitor" C0201_MURATA_GRM033_H0P3 72.475,35.35 r90 bottom value=1uF
C183 "Capacitor" C0603 46.848,43.214 r270 top value=22uF
C184 "Capacitor" C0603 45.895,32.764 r180 top value=10uF
C186 "Capacitor" C0805 52.798,30.389 r270 top value=22uF
C187 "Capacitor" C0805 49.198,30.389 r270 top value=22uF
C188 "Capacitor" C0402 44.923,27.179 r90 top value=1uF
C189 "Capacitor" C0402 44.098,27.179 r90 top value=4.7uF
C190 "Capacitor" C0402 46.148,27.654 r270 top value=4.7uF
C191 "Capacitor" C0201_MURATA_GRM033_H0P3 72.38,36.45 r90 bottom value=1uF
C192 "Capacitor" C0201_MURATA_GRM033_H0P3 73.9,31.9 r270 bottom value=1uF
C193 "Capacitor" C0805 35.198,43.939 r270 top value=22uF
C194 "Capacitor" C0201_MURATA_GRM033_H0P3 72.4,33.95 r270 bottom value=1uF
C195 "Capacitor" C0201_MURATA_GRM033_H0P3 70.05,32.35 r270 bottom value=1uF
C196 "Capacitor" C0201_MURATA_GRM033_H0P3 70.05,34.55 r90 bottom value=1uF
C197 "Capacitor" C0201_MURATA_GRM033_H0P3 68.5,34.55 r270 bottom value=1uF
C199 "Capacitor" C0603 33.073,32.739 r90 top value=10uF
C200 "Capacitor" C0603 26.173,35.189 r0 top value=22uF
C201 "Capacitor" C0201_MURATA_GRM033_H0P3 63.6,34.65 r0 top value=100nF
C202 "Capacitor" C0603 26.173,32.589 r0 top value=22uF
C203 "Capacitor" C0201_MURATA_GRM033_H0P3 71.425,34.575 r90 bottom value=1uF
C204 "Capacitor" C0805 28.098,29.312 r270 top value=22uF
C205 "Capacitor" C0201_MURATA_GRM033_H0P3 69.075,35.65 r270 bottom value=1uF
C206 "Capacitor" C0805 24.498,29.312 r270 top value=22uF
C207 "Capacitor" C0805 26.298,29.312 r270 top value=22uF
C208 "Capacitor" C0402 40.573,25.269 r270 top value=4.7uF
C209 "Capacitor" C0402 41.248,27.009 r90 top value=4.7uF
C210 "Capacitor" C0201_MURATA_GRM033_H0P3 70.88,36.83 r90 bottom value=100nF
C211 "Capacitor" C0201_MURATA_GRM033_H0P3 73.9,34.1 r90 bottom value=1uF
C212 "Capacitor" C0201_MURATA_GRM033_H0P3 69.05,36.75 r270 bottom value=100nF
C213 "Capacitor" C0201_MURATA_GRM033_H0P3 70.05,35.65 r90 bottom value=1uF
C214 "Capacitor" C0201_MURATA_GRM033_H0P3 71.475,27.375 r90 top value=1uF
C215 "Capacitor" C0201_MURATA_GRM033_H0P3 66.25,37.745 r180 bottom value=100nF
C217 "Capacitor" C0402 35.623,28.009 r270 top value=4.7uF
C219 "Capacitor" C0201_MURATA_GRM033_H0P3 70.05,36.75 r270 bottom value=100nF
C220 "Capacitor" C0201_MURATA_GRM033_H0P3 67.755,38.05 r0 bottom value=100nF
C225 "Capacitor" C0201_H0P5 68.995,33.35 r270 bottom value=4.7uF
C234 "Capacitor" C0201_MURATA_GRM033_H0P3 68.07,31.97 r90 bottom value=100nF
C235 "Capacitor" C0201_H0P5 67.375,33.2 r270 bottom value=2.2uF
C236 "Capacitor" C0201_MURATA_GRM033_H0P3 67.88,34.55 r90 bottom value=100nF
C237 "Capacitor" C0201_MURATA_GRM033_H0P3 67.38,37.225 r270 bottom value=100nF
C238 "Capacitor" C0201_MURATA_GRM033_H0P3 73.725,37.56 r180 bottom value=100nF
C240 "Capacitor" C0201_MURATA_GRM033_H0P3 68.045,35.775 r270 bottom value=100nF
C244 "Capacitor" C0201_MURATA_GRM033_H0P3 68.07,33.33 r270 bottom value=100nF
C246 "Capacitor" C0201_MURATA_GRM033_H0P3 71.95,30.47 r90 bottom value=100nF
C248 "Capacitor" C0201_MURATA_GRM033_H0P3 65.95,30.325 r90 bottom value=100nF
C250 "Capacitor" C0201_MURATA_GRM033_H0P3 66.5,30.325 r90 bottom value=1uF
C251 "Capacitor" C0201_MURATA_GRM033_H0P3 73.05,31.2 r270 bottom value=100nF
C253 "Capacitor" C0201_MURATA_GRM033_H0P3 71.4,30.47 r90 bottom value=100nF
C260 "Capacitor" C0201_MURATA_GRM033_H0P3 73.525,27.375 r90 top value=1uF
C283 "Capacitor" C0201_MURATA_GRM033_H0P3 72.675,33.125 r180 bottom value=1uF
C284 "Capacitor" C0201_MURATA_GRM033_H0P3 73.9,30.8 r90 bottom value=1uF
C287 "Capacitor" C0201_MURATA_GRM033_H0P3 71.5,36.825 r270 bottom value=1uF
C289 "Capacitor" C0201_MURATA_GRM033_H0P3 70.1,33.45 r90 bottom value=1uF
C299 "Capacitor" C0201_MURATA_GRM033_H0P3 71.4,35.68 r270 bottom value=1uF
C300 "Capacitor" C0201_MURATA_GRM033_H0P3 69.05,32.15 r90 bottom value=1uF
C304 "Capacitor" C0201_MURATA_GRM033_H0P3 73.9,36.425 r90 bottom value=1uF
C306 "Capacitor" C0201_MURATA_GRM033_H0P3 73.9,33 r270 bottom value=1uF
C307 "Capacitor" C0201_MURATA_GRM033_H0P3 69.05,34.55 r90 bottom value=1uF
CN12 "Header 2x1" CON_MOLEX_53047-0210 68.699,21.141 r0 bottom
D6 "DIODE_3P_DUAL_COMMON_CATHODE" DIO_SOT23 67.726,26.042 r270 bottom value=BAT54CFILM
D7 "BAT60JFILM" DIO_SOD323 83.93,52.788 r180 bottom
L1 "Inductor" IND_2016_MURATA_LQM2MPN2R2NG0 37.693,41.314 r180 top value=2.2uH
L2 "Inductor" IND_2520_TOKO_DFE252012P 45.813,40.589 r0 top value=0.68µH
L3 "Inductor" IND_2016_MURATA_LQM2MPN2R2NG0 32.748,39.214 r90 top value=0.68uH
L4 "Inductor" IND_2520_TOKO_DFE252012P 47.323,34.739 r0 top value=0.68µH
L5 "Inductor" IND_2016_MURATA_LQM2MPN2R2NG0 29.923,32.839 r180 top value=0.68uH
L6 "Inductor" IND_2016_MURATA_LQM2MPN2R2NG0 46.398,30.139 r0 top value=2.2uH
L7 "Inductor" IND_2016_MURATA_LQM2MPN2R2NG0 32.298,28.189 r180 top value=0.68uH
LD11 "LED_green" LED_0603_OSRAM_LG-Q396-PS-35_GREEN_1A2K_H0P4 22.284,25.411 r270 top value=GREEN
LNK1 "link_200" LINK200 39.998,42.262 r0 top
LNK2 "link_200" LINK200 55.439,34.839 r90 top
LNK4 "link_200" LINK200 29.748,39.264 r180 top
LNK7 "link_200" LINK200 51.848,33.489 r270 top
LNK8 "link_200" LINK200 27.598,35.637 r0 top
LNK11 "link_200" LINK200 53.998,29.579 r180 top
R2 "" R0402 34.478,25.834 r90 top value=0R
R3 "Resistor" R0402 63.531,30.192 r0 top value=0R
R11 "Resistor" R0603 74.475,26.775 r90 top value=0R
R26 "Resistor" R0402 89.975,40.435 r0 top value=10K
R27 "Resistor" R0402 65.225,26.95 r270 top value=10K
R46 "" R0402 42.048,40.137 r270 top value=0R
R57 "" R0402 42.748,26.089 r90 top value=0R
R59 "" R0402 32.378,25.834 r90 top value=0R
R60 "" R0402 33.428,25.834 r90 top value=0R
R64 "Resistor" R0402 63.312,33.195 r180 top value=0R
R66 "Resistor" R0402 67.866,23.699 r0 bottom value=20R
R67 "Resistor" R0402 70.199,27.491 r90 bottom value=0R
R81 "" R0402 42.061,42.487 r270 top value=0R
R94 "Resistor" R0201_H0P23 79.425,33.35 r0 bottom value=240R
R101 "Resistor" R0402 79.211,47.608 r90 bottom value=10K
R103 "Resistor" R0402 85.007,48.794 r90 bottom value=10K
R104 "Resistor" R0402 85.011,47.088 r270 bottom value=10K
R112 "Resistor" R0201_H0P23 76.2,33.55 r90 top value=240R
R210 "Resistor" R0402 22.284,27.604 r270 top value=270R
R248 "Resistor" R0402 85.493,50.263 r0 bottom value=10K
R260 "Resistor" R0402 39.704,40.267 r270 bottom value=1K5
R261 "Resistor" R0402 40.679,40.267 r270 bottom value=1K5
R267 "Resistor" R0402 66.5,33.05 r90 bottom value=0R
R269 "Resistor" R0402 65.55,33.05 r270 bottom value=0R
R272 "Resistor" R0402 32.849,24.016 r0 bottom value=10K
R286 "Resistor" R0402 74.375,26.975 r90 bottom value=0R
TP21 "Test Point" TP_SMD_1MM 83.352,46.948 r90 bottom value=N/A
U10 "MT53E1G16D1ZW-046 AIT:C" ICC_TFBGA200_10X14P5_P080_H1P05 85.9,34.65 r90 top
U14 "STM32MP257FAL3" ICC_VFBGA361_10X10_P050 70.475,34.15 r0 top locked
U26 "STPMIC25APQR" ICC_QFN56-EPAD_6P5X6P5_P040 39.398,33.939 r90 top
U37 "eMMC_THGBMTG5D1LBAIL" ICC_P-WFBGA153_13X11P5_P050 82.5,49.7 r0 top locked value=THGBMTG5D1LBAIL
X1 "XTAL_2_PINS" CRY_NX2012SA_2P 60.886,32.845 r270 top value=32.768KHz
X2 "XTAL_4_PINS" CRY_NX1612SA_4P 62.331,28.781 r180 top value=40MHz

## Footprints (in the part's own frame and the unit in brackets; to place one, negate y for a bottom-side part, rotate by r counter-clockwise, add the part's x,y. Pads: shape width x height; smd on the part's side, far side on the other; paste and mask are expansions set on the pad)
C0201_H0P5 [mm] "MCD-01534"
  rect 0.4x0.5 smd mask+0.05: 1(-0.3,0) 2(0.3,0)
  body extent -0.35,-0.2 0.35,0.2, height 0.55
C0201_MURATA_GRM033_H0P3 [mm] "GRM033R60J105ME11"
  rect 0.35x0.35 smd mask+0.05: 1(-0.275,0) 2(0.275,0)
  body extent -0.32,-0.17 0.32,0.17, height 0.33
C0402 [mm]
  rect 0.51x0.56 smd mask+0.05: 1(-0.45,0) 2(0.45,0)
  body extent -0.5,-0.3 0.5,0.3, height 0.4
C0603 [mm]
  rect 0.64x0.89 smd mask+0.05: 1(-0.7,0) 2(0.7,0)
  silkscreen extent -1.05,-0.55 1.02,0.55, body extent -0.9,-0.5 0.9,0.5, height 1.4
C0805 [mm]
  rect 0.9x1.4 smd mask+0.05: 1(-0.85,0) 2(0.85,0)
  silkscreen extent -1.3,-0.77 1.3,0.77, body extent -1.1,-0.7 1.1,0.7, height 1.35
CON_MOLEX_53047-0210 [mm]
  oval 1x1.3 hole 0.5 mask+0.05: 1(-0.625,0) 2(0.625,0)
  silkscreen extent -2.12,-1.15 2.13,2.05, body extent -2.12,-1.15 2.13,2.05, height 4.2
CPOL_TCJ-B_1210_H210 [mm] "MCD-01791"
  rect 1.35x2.8 smd mask+0.05: 1(-1.375,0) 2(1.375,0)
  silkscreen extent -2.33,-1.68 1.85,1.68, body extent -1.85,-1.5 1.85,1.5, height 2.11
CRY_NX1612SA_4P [mm] "MCD-02262"
  rect 0.75x0.6 smd mask+0.038: 1(-0.525,-0.375) 2(0.525,-0.375) 3(0.525,0.375) 4(-0.525,0.375)
  silkscreen extent -1.02,-0.8 0.03,0.6, body extent -0.8,-0.6 0.8,0.6, height 0.51
CRY_NX2012SA_2P [mm]
  rect 1x1.25 smd mask+0.05: 1(-0.75,0) 2(0.75,0)
  silkscreen extent -1.05,-0.75 1.05,0.75, body extent -1.05,-0.63 1.05,0.63, height 0.6
DIO_SOD323 [mm]
  rect 1.06x0.54 smd mask+0.05: 1(-1.07,0) 2(1.07,0)
  silkscreen extent -0.9,-0.72 0.9,0.72, body extent -1.3,-0.78 1.3,0.78, height 1.17
DIO_SOT23 [mm]
  rect 1x1.4 smd mask+0.05: 1(-0.95,-1.1) 2(0.95,-1.1) 3(0,1.1)
  silkscreen extent -1.63,-0.82 1.63,0.82, body extent -1.56,-1.25 1.56,1.25, height 1.1
ICC_P-WFBGA153_13X11P5_P050 [mm]
  round 0.23 smd mask+0.05: A1(-3.25,-3.25) A2(-3.25,-2.75) A3(-3.25,-2.25) A4(-3.25,-1.75) A5(-3.25,-1.25) A6(-3.25,-0.75) A7(-3.25,-0.25) A8(-3.25,0.25) A9(-3.25,0.75) A10(-3.25,1.25) A11(-3.25,1.75) A12(-3.25,2.25) A13(-3.25,2.75) A14(-3.25,3.25) B1(-2.75,-3.25) B2(-2.75,-2.75) B3(-2.75,-2.25) B4(-2.75,-1.75) B5(-2.75,-1.25) B6(-2.75,-0.75) B7(-2.75,-0.25) B8(-2.75,0.25) B9(-2.75,0.75) B10(-2.75,1.25) B11(-2.75,1.75) B12(-2.75,2.25) B13(-2.75,2.75) B14(-2.75,3.25) C1(-2.25,-3.25) C2(-2.25,-2.75) C3(-2.25,-2.25) C4(-2.25,-1.75) C5(-2.25,-1.25) C6(-2.25,-0.75) C7(-2.25,-0.25) C8(-2.25,0.25) C9(-2.25,0.75) C10(-2.25,1.25) C11(-2.25,1.75) C12(-2.25,2.25) C13(-2.25,2.75) C14(-2.25,3.25) D1(-1.75,-3.25) D2(-1.75,-2.75) D3(-1.75,-2.25) D4(-1.75,-1.75) D12(-1.75,2.25) D13(-1.75,2.75) D14(-1.75,3.25) E1(-1.25,-3.25) E2(-1.25,-2.75) E3(-1.25,-2.25) E5(-1.25,-1.25) E6(-1.25,-0.75) E7(-1.25,-0.25) E8(-1.25,0.25) E9(-1.25,0.75) E10(-1.25,1.25) E12(-1.25,2.25) E13(-1.25,2.75) E14(-1.25,3.25) F1(-0.75,-3.25) F2(-0.75,-2.75) F3(-0.75,-2.25) F5(-0.75,-1.25) F10(-0.75,1.25) F12(-0.75,2.25) F13(-0.75,2.75) F14(-0.75,3.25) G1(-0.25,-3.25) G2(-0.25,-2.75) G3(-0.25,-2.25) G5(-0.25,-1.25) G10(-0.25,1.25) G12(-0.25,2.25) G13(-0.25,2.75) G14(-0.25,3.25) H1(0.25,-3.25) H2(0.25,-2.75) H3(0.25,-2.25) H5(0.25,-1.25) H10(0.25,1.25) H12(0.25,2.25) H13(0.25,2.75) H14(0.25,3.25) J1(0.75,-3.25) J2(0.75,-2.75) J3(0.75,-2.25) J5(0.75,-1.25) J10(0.75,1.25) J12(0.75,2.25) J13(0.75,2.75) J14(0.75,3.25) K1(1.25,-3.25) K2(1.25,-2.75) K3(1.25,-2.25) K5(1.25,-1.25) K6(1.25,-0.75) K7(1.25,-0.25) K8(1.25,0.25) K9(1.25,0.75) K10(1.25,1.25) K12(1.25,2.25) K13(1.25,2.75) K14(1.25,3.25) L1(1.75,-3.25) L2(1.75,-2.75) L3(1.75,-2.25) L12(1.75,2.25) L13(1.75,2.75) L14(1.75,3.25) M1(2.25,-3.25) M2(2.25,-2.75) M3(2.25,-2.25) M4(2.25,-1.75) M5(2.25,-1.25) M6(2.25,-0.75) M7(2.25,-0.25) M8(2.25,0.25) M9(2.25,0.75) M10(2.25,1.25) M11(2.25,1.75) M12(2.25,2.25) M13(2.25,2.75) M14(2.25,3.25) N1(2.75,-3.25) N2(2.75,-2.75) N3(2.75,-2.25) N4(2.75,-1.75) N5(2.75,-1.25) N6(2.75,-0.75) N7(2.75,-0.25) N8(2.75,0.25) N9(2.75,0.75) N10(2.75,1.25) N11(2.75,1.75) N12(2.75,2.25) N13(2.75,2.75) N14(2.75,3.25) P1(3.25,-3.25) P2(3.25,-2.75) P3(3.25,-2.25) P4(3.25,-1.75) P5(3.25,-1.25) P6(3.25,-0.75) P7(3.25,-0.25) P8(3.25,0.25) P9(3.25,0.75) P10(3.25,1.25) P11(3.25,1.75) P12(3.25,2.25) P13(3.25,2.75) P14(3.25,3.25)
  silkscreen extent -6.78,-6.02 6.63,5.87, body extent -6.55,-5.8 6.55,5.8, height 1
ICC_QFN56-EPAD_6P5X6P5_P040 [mm] "MCD-03000"
  rect 0.55x0.21 smd mask+0.05: 1(-3.245,2.6) 14(-3.245,-2.6) 29(3.245,-2.6) 42(3.245,2.6)
  rect 0.7x0.21 smd mask+0.05: 2(-3.17,2.2) 3(-3.17,1.8) 4(-3.17,1.4) 5(-3.17,1) 6(-3.17,0.6) 7(-3.17,0.2) 8(-3.17,-0.2) 9(-3.17,-0.6) 10(-3.17,-1) 11(-3.17,-1.4) 12(-3.17,-1.8) 13(-3.17,-2.2) 30(3.17,-2.2) 31(3.17,-1.8) 32(3.17,-1.4) 33(3.17,-1) 34(3.17,-0.6) 35(3.17,-0.2) 36(3.17,0.2) 37(3.17,0.6) 38(3.17,1) 39(3.17,1.4) 40(3.17,1.8) 41(3.17,2.2)
  rect 0.21x0.55 smd mask+0.05: 15(-2.6,-3.245) 28(2.6,-3.245) 43(2.6,3.245) 56(-2.6,3.245)
  rect 0.21x0.7 smd mask+0.05: 16(-2.2,-3.17) 17(-1.8,-3.17) 18(-1.4,-3.17) 19(-1,-3.17) 20(-0.6,-3.17) 21(-0.2,-3.17) 22(0.2,-3.17) 23(0.6,-3.17) 24(1,-3.17) 25(1.4,-3.17) 26(1.8,-3.17) 27(2.2,-3.17) 44(2.2,3.17) 45(1.8,3.17) 46(1.4,3.17) 47(1,3.17) 48(0.6,3.17) 49(0.2,3.17) 50(-0.2,3.17) 51(-0.6,3.17) 52(-1,3.17) 53(-1.4,3.17) 54(-1.8,3.17) 55(-2.2,3.17)
  rect 4.7x4.7 smd mask+0.05: 57(0,0)
  Top Layer region: -2.97,2.495 -2.82,2.495 -2.82,2.555 -2.97,2.705
  Top Layer region: -2.97,-2.495 -2.82,-2.495 -2.82,-2.555 -2.97,-2.705
  Top Layer region: -2.495,2.97 -2.495,2.82 -2.555,2.82 -2.705,2.97
  Top Layer region: 2.97,-2.495 2.82,-2.495 2.82,-2.555 2.97,-2.705
  Top Layer region: 2.495,-2.97 2.495,-2.82 2.555,-2.82 2.705,-2.97
  Top Layer region: 2.97,2.495 2.82,2.495 2.82,2.555 2.97,2.705
  Top Layer region: 2.495,2.97 2.495,2.82 2.555,2.82 2.705,2.97
  Top Layer region: -2.495,-2.97 -2.495,-2.82 -2.555,-2.82 -2.705,-2.97
  silkscreen extent -3.44,3 -3.01,3.42, body extent -3.25,-3.25 3.25,3.25, height 0.91
ICC_TFBGA200_10X14P5_P080_H1P05 [mm]
  round 0.35 smd mask+0.05: A1(-4.4,6.825) A2(-3.6,6.825) A3(-2.8,6.825) A4(-2,6.825) A5(-1.2,6.825) A8(1.2,6.825) A9(2,6.825) A10(2.8,6.825) A11(3.6,6.825) A12(4.4,6.825) AA1(-4.4,-6.175) AA2(-3.6,-6.175) AA3(-2.8,-6.175) AA4(-2,-6.175) AA5(-1.2,-6.175) AA8(1.2,-6.175) AA9(2,-6.175) AA10(2.8,-6.175) AA11(3.6,-6.175) AA12(4.4,-6.175) AB1(-4.4,-6.825) AB2(-3.6,-6.825) AB3(-2.8,-6.825) AB4(-2,-6.825) AB5(-1.2,-6.825) AB8(1.2,-6.825) AB9(2,-6.825) AB10(2.8,-6.825) AB11(3.6,-6.825) AB12(4.4,-6.825) B1(-4.4,6.175) B2(-3.6,6.175) B3(-2.8,6.175) B4(-2,6.175) B5(-1.2,6.175) B8(1.2,6.175) B9(2,6.175) B10(2.8,6.175) B11(3.6,6.175) B12(4.4,6.175) C1(-4.4,5.525) C2(-3.6,5.525) C3(-2.8,5.525) C4(-2,5.525) C5(-1.2,5.525) C8(1.2,5.525) C9(2,5.525) C10(2.8,5.525) C11(3.6,5.525) C12(4.4,5.525) D1(-4.4,4.875) D2(-3.6,4.875) D3(-2.8,4.875) D4(-2,4.875) D5(-1.2,4.875) D8(1.2,4.875) D9(2,4.875) D10(2.8,4.875) D11(3.6,4.875) D12(4.4,4.875) E1(-4.4,4.225) E2(-3.6,4.225) E3(-2.8,4.225) E4(-2,4.225) E5(-1.2,4.225) E8(1.2,4.225) E9(2,4.225) E10(2.8,4.225) E11(3.6,4.225) E12(4.4,4.225) F1(-4.4,3.575) F2(-3.6,3.575) F3(-2.8,3.575) F4(-2,3.575) F5(-1.2,3.575) F8(1.2,3.575) F9(2,3.575) F10(2.8,3.575) F11(3.6,3.575) F12(4.4,3.575) G1(-4.4,2.925) G2(-3.6,2.925) G3(-2.8,2.925) G4(-2,2.925) G5(-1.2,2.925) G8(1.2,2.925) G9(2,2.925) G10(2.8,2.925) G11(3.6,2.925) G12(4.4,2.925) H1(-4.4,2.275) H2(-3.6,2.275) H3(-2.8,2.275) H4(-2,2.275) H5(-1.2,2.275) H8(1.2,2.275) H9(2,2.275) H10(2.8,2.275) H11(3.6,2.275) H12(4.4,2.275) J1(-4.4,1.625) J2(-3.6,1.625) J3(-2.8,1.625) J4(-2,1.625) J5(-1.2,1.625) J8(1.2,1.625) J9(2,1.625) J10(2.8,1.625) J11(3.6,1.65) J12(4.4,1.625) K1(-4.4,0.975) K2(-3.6,0.975) K3(-2.8,0.975) K4(-2,0.975) K5(-1.2,0.975) K8(1.2,0.975) K9(2,0.975) K10(2.8,0.975) K11(3.6,0.975) K12(4.4,0.975) N1(-4.4,-0.975) N2(-3.6,-0.975) N3(-2.8,-0.975) N4(-2,-0.975) N5(-1.2,-0.975) N8(1.2,-0.975) N9(2,-0.975) N10(2.8,-0.975) N11(3.6,-0.975) N12(4.4,-0.975) P1(-4.4,-1.625) P2(-3.6,-1.625) P3(-2.8,-1.625) P4(-2,-1.625) P5(-1.2,-1.625) P8(1.2,-1.625) P9(2,-1.625) P10(2.8,-1.625) P11(3.6,-1.625) P12(4.4,-1.625) R1(-4.4,-2.275) R2(-3.6,-2.275) R3(-2.8,-2.275) R4(-2,-2.275) R5(-1.2,-2.275) R8(1.2,-2.275) R9(2,-2.275) R10(2.8,-2.275) R11(3.6,-2.275) R12(4.4,-2.275) T1(-4.4,-2.925) T2(-3.6,-2.925) T3(-2.8,-2.925) T4(-2,-2.925) T5(-1.2,-2.925) T8(1.2,-2.925) T9(2,-2.925) T10(2.8,-2.925) T11(3.6,-2.925) T12(4.4,-2.925) U1(-4.4,-3.575) U2(-3.6,-3.575) U3(-2.8,-3.575) U4(-2,-3.575) U5(-1.2,-3.575) U8(1.2,-3.575) U9(2,-3.575) U10(2.8,-3.575) U11(3.6,-3.575) U12(4.4,-3.575) V1(-4.4,-4.225) V2(-3.6,-4.225) V3(-2.8,-4.225) V4(-2,-4.225) V5(-1.2,-4.225) V8(1.2,-4.225) V9(2,-4.225) V10(2.8,-4.225) V11(3.6,-4.225) V12(4.4,-4.225) W1(-4.4,-4.875) W2(-3.6,-4.875) W3(-2.8,-4.875) W4(-2,-4.875) W5(-1.2,-4.875) W8(1.2,-4.875) W9(2,-4.875) W10(2.8,-4.875) W11(3.6,-4.875) W12(4.4,-4.875) Y1(-4.4,-5.525) Y2(-3.6,-5.525) Y3(-2.8,-5.525) Y4(-2,-5.525) Y5(-1.2,-5.525) Y8(1.2,-5.525) Y9(2,-5.525) Y10(2.8,-5.525) Y11(3.6,-5.525) Y12(4.4,-5.525)
  silkscreen extent -5.2,-7.3 5.05,7.45, body extent -5.05,-7.3 5.05,7.3, height 1.06
ICC_VFBGA361_10X10_P050 [mm] "MCD-03768"
  round 0.23 smd mask+0.05: A1(-4.5,4.5) A2(-4,4.5) A3(-3.5,4.5) A4(-3,4.5) A5(-2.5,4.5) A6(-2,4.5) A7(-1.5,4.5) A8(-1,4.5) A9(-0.5,4.5) A10(0,4.5) A11(0.5,4.5) A12(1,4.5) A13(1.5,4.5) A14(2,4.5) A15(2.5,4.5) A16(3,4.5) A17(3.5,4.5) A18(4,4.5) A19(4.5,4.5) B1(-4.5,4) B2(-4,4) B3(-3.5,4) B4(-3,4) B5(-2.5,4) B6(-2,4) B7(-1.5,4) B8(-1,4) B9(-0.5,4) B10(0,4) B11(0.5,4) B12(1,4) B13(1.5,4) B14(2,4) B15(2.5,4) B16(3,4) B17(3.5,4) B18(4,4) B19(4.5,4) C1(-4.5,3.5) C2(-4,3.5) C3(-3.5,3.5) C4(-3,3.5) C5(-2.5,3.5) C6(-2,3.5) C7(-1.5,3.5) C8(-1,3.5) C9(-0.5,3.5) C10(0,3.5) C11(0.5,3.5) C12(1,3.5) C13(1.5,3.5) C14(2,3.5) C15(2.5,3.5) C16(3,3.5) C17(3.5,3.5) C18(4,3.5) C19(4.5,3.5) D1(-4.5,3) D2(-4,3) D3(-3.5,3) D4(-3,3) D5(-2.5,3) D6(-2,3) D7(-1.5,3) D8(-1,3) D9(-0.5,3) D10(0,3) D11(0.5,3) D12(1,3) D13(1.5,3) D14(2,3) D15(2.5,3) D16(3,3) D17(3.5,3) D18(4,3) D19(4.5,3) E1(-4.5,2.5) E2(-4,2.5) E3(-3.5,2.5) E4(-3,2.5) E5(-2.5,2.5) E6(-2,2.5) E7(-1.5,2.5) E8(-1,2.5) E9(-0.5,2.5) E10(0,2.5) E11(0.5,2.5) E12(1,2.5) E13(1.5,2.5) E14(2,2.5) E15(2.5,2.5) E16(3,2.5) E17(3.5,2.5) E18(4,2.5) E19(4.5,2.5) F1(-4.5,2) F2(-4,2) F3(-3.5,2) F4(-3,2) F5(-2.5,2) F6(-2,2) F7(-1.5,2) F8(-1,2) F9(-0.5,2) F10(0,2) F11(0.5,2) F12(1,2) F13(1.5,2) F14(2,2) F15(2.5,2) F16(3,2) F17(3.5,2) F18(4,2) F19(4.5,2) G1(-4.5,1.5) G2(-4,1.5) G3(-3.5,1.5) G4(-3,1.5) G5(-2.5,1.5) G6(-2,1.5) G7(-1.5,1.5) G8(-1,1.5) G9(-0.5,1.5) G10(0,1.5) G11(0.5,1.5) G12(1,1.5) G13(1.5,1.5) G14(2,1.5) G15(2.5,1.5) G16(3,1.5) G17(3.5,1.5) G18(4,1.5) G19(4.5,1.5) H1(-4.5,1) H2(-4,1) H3(-3.5,1) H4(-3,1) H5(-2.5,1) H6(-2,1) H7(-1.5,1) H8(-1,1) H9(-0.5,1) H10(0,1) H11(0.5,1) H12(1,1) H13(1.5,1) H14(2,1) H15(2.5,1) H16(3,1) H17(3.5,1) H18(4,1) H19(4.5,1) J1(-4.5,0.5) J2(-4,0.5) J3(-3.5,0.5) J4(-3,0.5) J5(-2.5,0.5) J6(-2,0.5) J7(-1.5,0.5) J8(-1,0.5) J9(-0.5,0.5) J10(0,0.5) J11(0.5,0.5) J12(1,0.5) J13(1.5,0.5) J14(2,0.5) J15(2.5,0.5) J16(3,0.5) J17(3.5,0.5) J18(4,0.5) J19(4.5,0.5) K1(-4.5,0) K2(-4,0) K3(-3.5,0) K4(-3,0) K5(-2.5,0) K6(-2,0) K7(-1.5,0) K8(-1,0) K9(-0.5,0) K10(0,0) K11(0.5,0) K12(1,0) K13(1.5,0) K14(2,0) K15(2.5,0) K16(3,0) K17(3.5,0) K18(4,0) K19(4.5,0) L1(-4.5,-0.5) L2(-4,-0.5) L3(-3.5,-0.5) L4(-3,-0.5) L5(-2.5,-0.5) L6(-2,-0.5) L7(-1.5,-0.5) L8(-1,-0.5) L9(-0.5,-0.5) L10(0,-0.5) L11(0.5,-0.5) L12(1,-0.5) L13(1.5,-0.5) L14(2,-0.5) L15(2.5,-0.5) L16(3,-0.5) L17(3.5,-0.5) L18(4,-0.5) L19(4.5,-0.5) M1(-4.5,-1) M2(-4,-1) M3(-3.5,-1) M4(-3,-1) M5(-2.5,-1) M6(-2,-1) M7(-1.5,-1) M8(-1,-1) M9(-0.5,-1) M10(0,-1) M11(0.5,-1) M12(1,-1) M13(1.5,-1) M14(2,-1) M15(2.5,-1) M16(3,-1) M17(3.5,-1) M18(4,-1) M19(4.5,-1) N1(-4.5,-1.5) N2(-4,-1.5) N3(-3.5,-1.5) N4(-3,-1.5) N5(-2.5,-1.5) N6(-2,-1.5) N7(-1.5,-1.5) N8(-1,-1.5) N9(-0.5,-1.5) N10(0,-1.5) N11(0.5,-1.5) N12(1,-1.5) N13(1.5,-1.5) N14(2,-1.5) N15(2.5,-1.5) N16(3,-1.5) N17(3.5,-1.5) N18(4,-1.5) N19(4.5,-1.5) P1(-4.5,-2) P2(-4,-2) P3(-3.5,-2) P4(-3,-2) P5(-2.5,-2) P6(-2,-2) P7(-1.5,-2) P8(-1,-2) P9(-0.5,-2) P10(0,-2) P11(0.5,-2) P12(1,-2) P13(1.5,-2) P14(2,-2) P15(2.5,-2) P16(3,-2) P17(3.5,-2) P18(4,-2) P19(4.5,-2) R1(-4.5,-2.5) R2(-4,-2.5) R3(-3.5,-2.5) R4(-3,-2.5) R5(-2.5,-2.5) R6(-2,-2.5) R7(-1.5,-2.5) R8(-1,-2.5) R9(-0.5,-2.5) R10(0,-2.5) R11(0.5,-2.5) R12(1,-2.5) R13(1.5,-2.5) R14(2,-2.5) R15(2.5,-2.5) R16(3,-2.5) R17(3.5,-2.5) R18(4,-2.5) R19(4.5,-2.5) T1(-4.5,-3) T2(-4,-3) T3(-3.5,-3) T4(-3,-3) T5(-2.5,-3) T6(-2,-3) T7(-1.5,-3) T8(-1,-3) T9(-0.5,-3) T10(0,-3) T11(0.5,-3) T12(1,-3) T13(1.5,-3) T14(2,-3) T15(2.5,-3) T16(3,-3) T17(3.5,-3) T18(4,-3) T19(4.5,-3) U1(-4.5,-3.5) U2(-4,-3.5) U3(-3.5,-3.5) U4(-3,-3.5) U5(-2.5,-3.5) U6(-2,-3.5) U7(-1.5,-3.5) U8(-1,-3.5) U9(-0.5,-3.5) U10(0,-3.5) U11(0.5,-3.5) U12(1,-3.5) U13(1.5,-3.5) U14(2,-3.5) U15(2.5,-3.5) U16(3,-3.5) U17(3.5,-3.5) U18(4,-3.5) U19(4.5,-3.5) V1(-4.5,-4) V2(-4,-4) V3(-3.5,-4) V4(-3,-4) V5(-2.5,-4) V6(-2,-4) V7(-1.5,-4) V8(-1,-4) V9(-0.5,-4) V10(0,-4) V11(0.5,-4) V12(1,-4) V13(1.5,-4) V14(2,-4) V15(2.5,-4) V16(3,-4) V17(3.5,-4) V18(4,-4) V19(4.5,-4) W1(-4.5,-4.5) W2(-4,-4.5) W3(-3.5,-4.5) W4(-3,-4.5) W5(-2.5,-4.5) W6(-2,-4.5) W7(-1.5,-4.5) W8(-1,-4.5) W9(-0.5,-4.5) W10(0,-4.5) W11(0.5,-4.5) W12(1,-4.5) W13(1.5,-4.5) W14(2,-4.5) W15(2.5,-4.5) W16(3,-4.5) W17(3.5,-4.5) W18(4,-4.5) W19(4.5,-4.5)
  silkscreen extent -5.25,-5 5,5.2, body extent -5,-5 5,5, height 0.82
IND_2016_MURATA_LQM2MPN2R2NG0 [mm] "MCD-03141"
  rect 0.8x1.8 smd mask+0.05: 1(-0.8,0) 2(0.8,0)
  silkscreen extent -0.28,-0.87 0.28,0.87, body extent -1.07,-0.87 1.08,0.87, height 1
IND_2520_TOKO_DFE252012P [mm] "MCD-02254"
  rect 0.8x2 smd mask+0.05: 1(-1,0) 2(1,0)
  silkscreen extent -1.35,-1.12 1.35,1.12, body extent -1.35,-1.1 1.35,1.1, height 2
LED_0603_OSRAM_LG-Q396-PS-35_GREEN_1A2K_H0P4 [mm]
  rect 0.8x0.8 smd mask+0.05: 1(-0.75,0) 2(0.75,0)
  silkscreen extent -0.85,-0.53 1.28,0.53, body extent -0.85,-0.45 0.85,0.45, height 0.6
LINK200 [mm]
  rect 0.2x0.35 smd paste-10 mask+0.05: 1(0,-0.225) 2(0,0.225)
R0201_H0P23 [mm]
  rect 0.4x0.5 smd mask+0.05: 1(-0.3,0) 2(0.3,0)
  body extent -0.32,-0.17 0.32,0.17, height 0.26
R0402 [mm]
  rect 0.51x0.7 smd mask+0.05: 1(-0.45,0) 2(0.45,0)
  body extent -0.52,-0.3 0.52,0.3, height 0.4
R0603 [mm]
  rect 0.64x1 smd mask+0.05: 1(-0.7,0) 2(0.7,0)
  silkscreen extent -1.05,-0.58 1.05,0.58, body extent -0.9,-0.5 0.9,0.5, height 0.56
SWI_WE_434121025816 [mm] "MCD-03492"
  rect 1.5x1.4 smd: 1(-3.25,0) 2(3.25,0)
  silkscreen extent -3,-1.95 3,1.95, body extent -3.65,-1.95 3.65,1.95, height 2.51
TP_SMD_1MM [mm]
  round 1 smd paste-10 mask+0.05: 1(0,0)
  silkscreen extent -0.7,-0.7 0.7,0.7

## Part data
B2: library part MCD-03492, "Switch tactile, SPST-NO, 50mA, 12V, 6x3.8mm", Manufacturer="WURTH ELEKTRONIC", Manufacturer_Part_Number=434121025816, Package=6x3.8mm
C1 C2 C3 C4 C5 C15 C214 C250 C260: library part MCD-02377, "Capacitor, MLCC, 1uF, 6.3V, X5R, +/-20%, 0201, T=0,3mm", Manufacturer=MURATA, Manufacturer_Part_Number=GRM033R60J105MEA2, Package=0201
C9 C52 C53 C54 C55 C56 C57 C58 C59 C60 C61 C64 C65 C66 C67 C68 C87 C118 C130: library part MCD-00006, "Capacitor, MLCC, 100nF, 16V, X7R, +/-10%, 0402, T=0.5mm", Manufacturer=YAGEO, Manufacturer_Part_Number=CC0402KRX7R7BB104, Package=0402
C14: library part MCD-01823, "Capacitor, MLCC, 2.2uF, 6V3, X5R,+/-10%, 0402, T=0.5mm", Manufacturer=MURATA, Manufacturer_Part_Number=GRM155R60J225KE95D, Package=0402
C16 C17 C201 C210 C212 C215 C219 C220 C234 C236 C237 C238 C240 C244 C246 C248 C251 C253: library part MCD-01535, "Capacitor, MLCC,100nF, 10V, X5R, +/-10%, 0201, T=0.3mm", Manufacturer=MURATA, Manufacturer_Part_Number=GRM033R61A104KE15, Package=0201
C18 C42: library part MCD-01796, "Capacitor, Tantalum, 100uF, 6V3, 40mR, +/-20%,  Type_B (3528 metric), T=1.9mm", Manufacturer=AVX, Manufacturer_Part_Number=TCJB107M006R0040, Package="3528 (metric)"
C19 C21 C152 C157 C186 C187 C193 C204 C206 C207: library part MCD-03139, "Capacitor, MLCC, 22uF, 10V, X5R, +/-20%, 0805, T=1,25mm", Manufacturer=MURATA, Manufacturer_Part_Number=GRM21BR61A226ME51L, Package=0805
C20 C29 C30 C32 C38 C184 C199: library part MCD-00099, "Capacitor, MLCC, 10uF, 10V, X5R, +/-10%, 0603, T=0,8mm", Alternate_Manufacturer=N/A, Manufacturer=MURATA, Manufacturer_Part_Number=GRM188R61A106KE69D, Package=0603
C22 C23 C24 C26 C27 C28 C34 C35 C36 C37 C41 C183 C200 C202: library part MCD-00100, "Capacitor, MLCC, 22uF, 6V3, X5R, +/-20%, 0603, T=0,8mm", Alternate_Manufacturer=N/A, Manufacturer=MURATA, Manufacturer_Part_Number=GRM188R60J226MEA0J, Package=0603
C33: library part MCD-00011, "Capacitor, MLCC, 10nF, 16V, X7R, +/-10%, 0402, T=0.5mm", Manufacturer=YAGEO, Manufacturer_Part_Number=CC0402KRX7R7BB103, Package=0402
C39 C43 C153 C154 C188: library part MCD-00095, "Capacitor, MLCC, 1uF, 25V, X5R, +/-10%, 0402, T=0.5mm", Manufacturer=MURATA, Manufacturer_Part_Number=GRM155R61E105KA12, Package=0402
C40: library part MCD-03140, "Capacitor, MLCC, 10uF, 6.3V, X5R, +/-20%, 0402, T=0.5mm", Manufacturer=MURATA, Manufacturer_Part_Number=GRM155R60J106ME05D, Package=0402
C50 C51 C62 C63: library part MCD-01341, "Capacitor, MLCC, 10uF, 6V3, X5R, +/-20%, 0603, T=0.8mm", Manufacturer=MURATA, Manufacturer_Part_Number=GRM188R60J106ME47D, Package=0603
C79 C117 C128: library part MCD-02606, "Capacitor, MLCC, 2.2uF, 6.3V, X5R, +/-10%, 0402, T=0.5mm", Manufacturer=YAGEO, Manufacturer_Part_Number=CC0402KRX5R5BB225, Package=0402
C81 C86 C90 C92: library part MCD-00674, "Capacitor, MLCC, 6.8pF, 50V, NPO, +/-0.25pF, 0402, T=0.5mm", Manufacturer=YAGEO, Manufacturer_Part_Number=CC0402CRNPO9BN6R8, Package=0402
C91 C141 C142 C156 C189 C190 C208 C209 C217: library part MCD-01356, "Capacitor, MLCC, 4.7uF, 6V3, X5R, +/-20%, 0402, T=0.5mm", Manufacturer=MURATA, Manufacturer_Part_Number=GRM155R60J475ME47, Package=0402
C155: library part MCD-02198, "Capacitor, MLCC, 10nF, 50V, X7R, +/-10%, 0402, T=0.5mm", Manufacturer=YAGEO, Manufacturer_Part_Number=CC0402KRX7R9BB103, Package=0402
C175 C177 C191 C192 C194 C195 C196 C197 C203 C205 C211 C213 C283 C284 C287 C289 C299 C300 C304 C306 C307: library part MCD-01533, "Capacitor, MLCC, 1uF, 6V3, X5R, +/-20%, 0201, T=0.3mm", Manufacturer=MURATA, Manufacturer_Part_Number=GRM033R60J105ME11, Package=0201
C225: library part MCD-01534, "Capacitor, MLCC, 4,7uF, 6V3, X5R, +/-20%, 0201, T=0.5mm", Manufacturer=MURATA, Manufacturer_Part_Number=GRM035R60J475ME15, Package=0201
C235: library part MCD-02235, "Capacitor, MLCC, 2.2uF, 10V, X5R,+/-10%, 0201, T=0.5mm", Manufacturer=MURATA, Manufacturer_Part_Number=GRM033R61A225KE47D, Package=0201
CN12: library part MCD-00655, "Header, 2x1, 1.25mm, VR, TH, T=2.25mm/2.3mm", Manufacturer=MOLEX, Manufacturer_Part_Number=53047-0210
D6: library part MCD-03280, "Diode, Schottky, Dual Common Cathode, 0V3, 300mA, 40V, SOT-23", Manufacturer=STMICROELECTRONICS, Manufacturer_Part_Number=BAT54CFILM, Package=SOT23
D7: library part MCD-00034, "Diode, Schottky, 0V53, 1A, 10V, SOD323", Manufacturer=STMICROELECTRONICS, Manufacturer_HQ_COO=EU, Package=SOD323
L1 L6: library part MCD-03143, "Inductor, 2.2uH, +/-20%, Itemp= 1700mA, Isat= 2400mA, 0R140, 0806, T=1mm", Manufacturer=MURATA, Manufacturer_Part_Number=DFE201610E-2R2M{}P2, Package=0806
L2 L4: library part MCD-03142, "Inductor, 0.68uH, +/-20%, Itemp= 3900mA, Isat= 5400mA, 0R031, 1008, T=1.2mm", Manufacturer=MURATA, Manufacturer_Part_Number=DFE252012F-R68M{}P2, Package=1008
L3 L5 L7: library part MCD-03141, "Inductor, 0.68uH, +/-20%, Itemp= 3100mA, Isat= 4300mA, 0R043, 0806, T=1mm", Manufacturer=MURATA, Manufacturer_Part_Number=DFE201610E-R68M{}P2, Package=0806
LD11: library part MCD-00588, "LED Green, 0603 SMD, Forward Voltage Typ=2V, Max=2.5V", Alternate_Manufacturer="VISHAY SEMICONDUCTOR OPTO DIVISION", Alternate_Manufacturer_Part_Number=VLMTG1300-GS08, Manufacturer="OSRAM OPTO SEMICONDUCTORS", Manufacturer_Part_Number="LG Q396-PS-35", Package="LED 0603"
LNK1 LNK2 LNK4 LNK7 LNK8 LNK11: library part MCD-02777, "Track link on PCB 200um width for layout routing", Manufacturer=N/A
R2 R46 R57 R59 R60 R81: library part MCD-00052, "Resistor,0R,0402,5%,1/16W", Alternate_Manufacturer=N/A, Manufacturer=YAGEO, Manufacturer_Part_Number=RC0402JR-070RL, Package=0402
R3 R64 R67 R267 R269 R286: library part MCD-00052, "Resistor, 0R, 0402, +/-5%, 1/16W", Manufacturer=YAGEO, Manufacturer_Part_Number=RC0402JR-070RL, Package=0402
R11: library part MCD-00056, "Resistor, 0R, 0603, +/-5%, 1/10W", Manufacturer=YAGEO, Manufacturer_Part_Number=RC0603JR-070RL, Package=0603
R26 R27 R101 R103 R104 R248 R272: library part MCD-00053, "Resistor, 10K, 0402, +/-1%, 1/16W", Manufacturer=YAGEO, Manufacturer_Part_Number=RC0402FR-0710KL, Package=0402
R66: library part MCD-00058, "Resistor, 20R, 0402, +/-1%, 1/16W", Manufacturer=YAGEO, Manufacturer_Part_Number=RC0402FR-0720RL, Package=0402
R94 R112: library part MCD-02253, "Resistor, 240R, 0201, +/-1%, 1/20W", Manufacturer=YAGEO, Manufacturer_Part_Number=RC0201FR-07240RL, Package=0201
R210: library part MCD-00441, "Resistor,270R,0402,1%,1/16W", Manufacturer=YAGEO, Manufacturer_Part_Number=RC0402FR-07270RL, Package=0402
R260 R261: library part MCD-00068, "Resistor, 1K5, 0402, +/-1%, 1/16W", Manufacturer=YAGEO, Manufacturer_Part_Number=RC0402FR-071K5L, Package=0402
TP21: library part MCD-00074, "Test Point, SMD, 1mm", Manufacturer=N/A, Manufacturer_HQ_COO=Unknown
U10: library part MCD-04012, "Memory, SDRAM, 1V1, 16Gbit, 4266Mhz", Manufacturer=MICRON, Package="TFBGA200 10x14.5mm"
U14: library part MCD-03768, "MPU, dual core ARM cortex-A35 64-bit + M33 32-bit, 808KB SRAM, With Crypto", Manufacturer=STMICROELECTRONICS, Package=VFBGA361
U26: library part MCD-03000, "STPMIC2", Manufacturer=STMICROELECTRONICS, Package=VQFN
U37: library part MCD-02799, "Memory, eMMC, 3V3, 4Gbit, 52MHz", Manufacturer=KIOXIA, Manufacturer_Part_Number=THGBMTG5D1LBAIL, Package=WFBGA153
X1: library part MCD-01479, "Crystal, 32.768kHz, 6pF, +/-20ppm, 80K, 2.05x1.2mm", Manufacturer=NDK, Manufacturer_Part_Number=NX2012SA-32.768KHZ-EXS00A-MU00527, Package=2.05x1.2mm
X2: library part MCD-02344, "Crystal, 40MHz, 6pF, +/-20ppm, 80R, 1.6x1.2mm", Manufacturer=NDK, Manufacturer_Part_Number=NX1612SA-40MHZ-EXS00A-CS13836, Package=1.6x1.2mm

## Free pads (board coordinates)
  round 0.508 on Mech16: 1(39.085,-32.513) 1(87.94,-32.521)

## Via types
v1: diameter 0.26, hole 0.1, Top Layer to Signal Layer 1, 266 vias
v2: diameter 0.5, hole 0.2, Top Layer to Bottom Layer, 216 vias
v3: diameter 0.26, hole 0.1, Signal Layer 1 to Signal Layer 2, 138 vias
v4: diameter 0.4, hole 0.2, Signal Layer 1 to Signal Layer 4, 99 vias
v5: diameter 0.4, hole 0.2, Top Layer to Bottom Layer, tented both sides, 94 vias
v6: diameter 0.26, hole 0.1, Signal Layer 4 to Bottom Layer, 82 vias
v7: diameter 0.55, hole 0.35, Top Layer to Bottom Layer, 55 vias
v8: diameter 0.55, hole 0.3, Top Layer to Bottom Layer, 7 vias
v9: diameter 0.5, hole 0.2, Signal Layer 1 to Signal Layer 4, 1 vias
